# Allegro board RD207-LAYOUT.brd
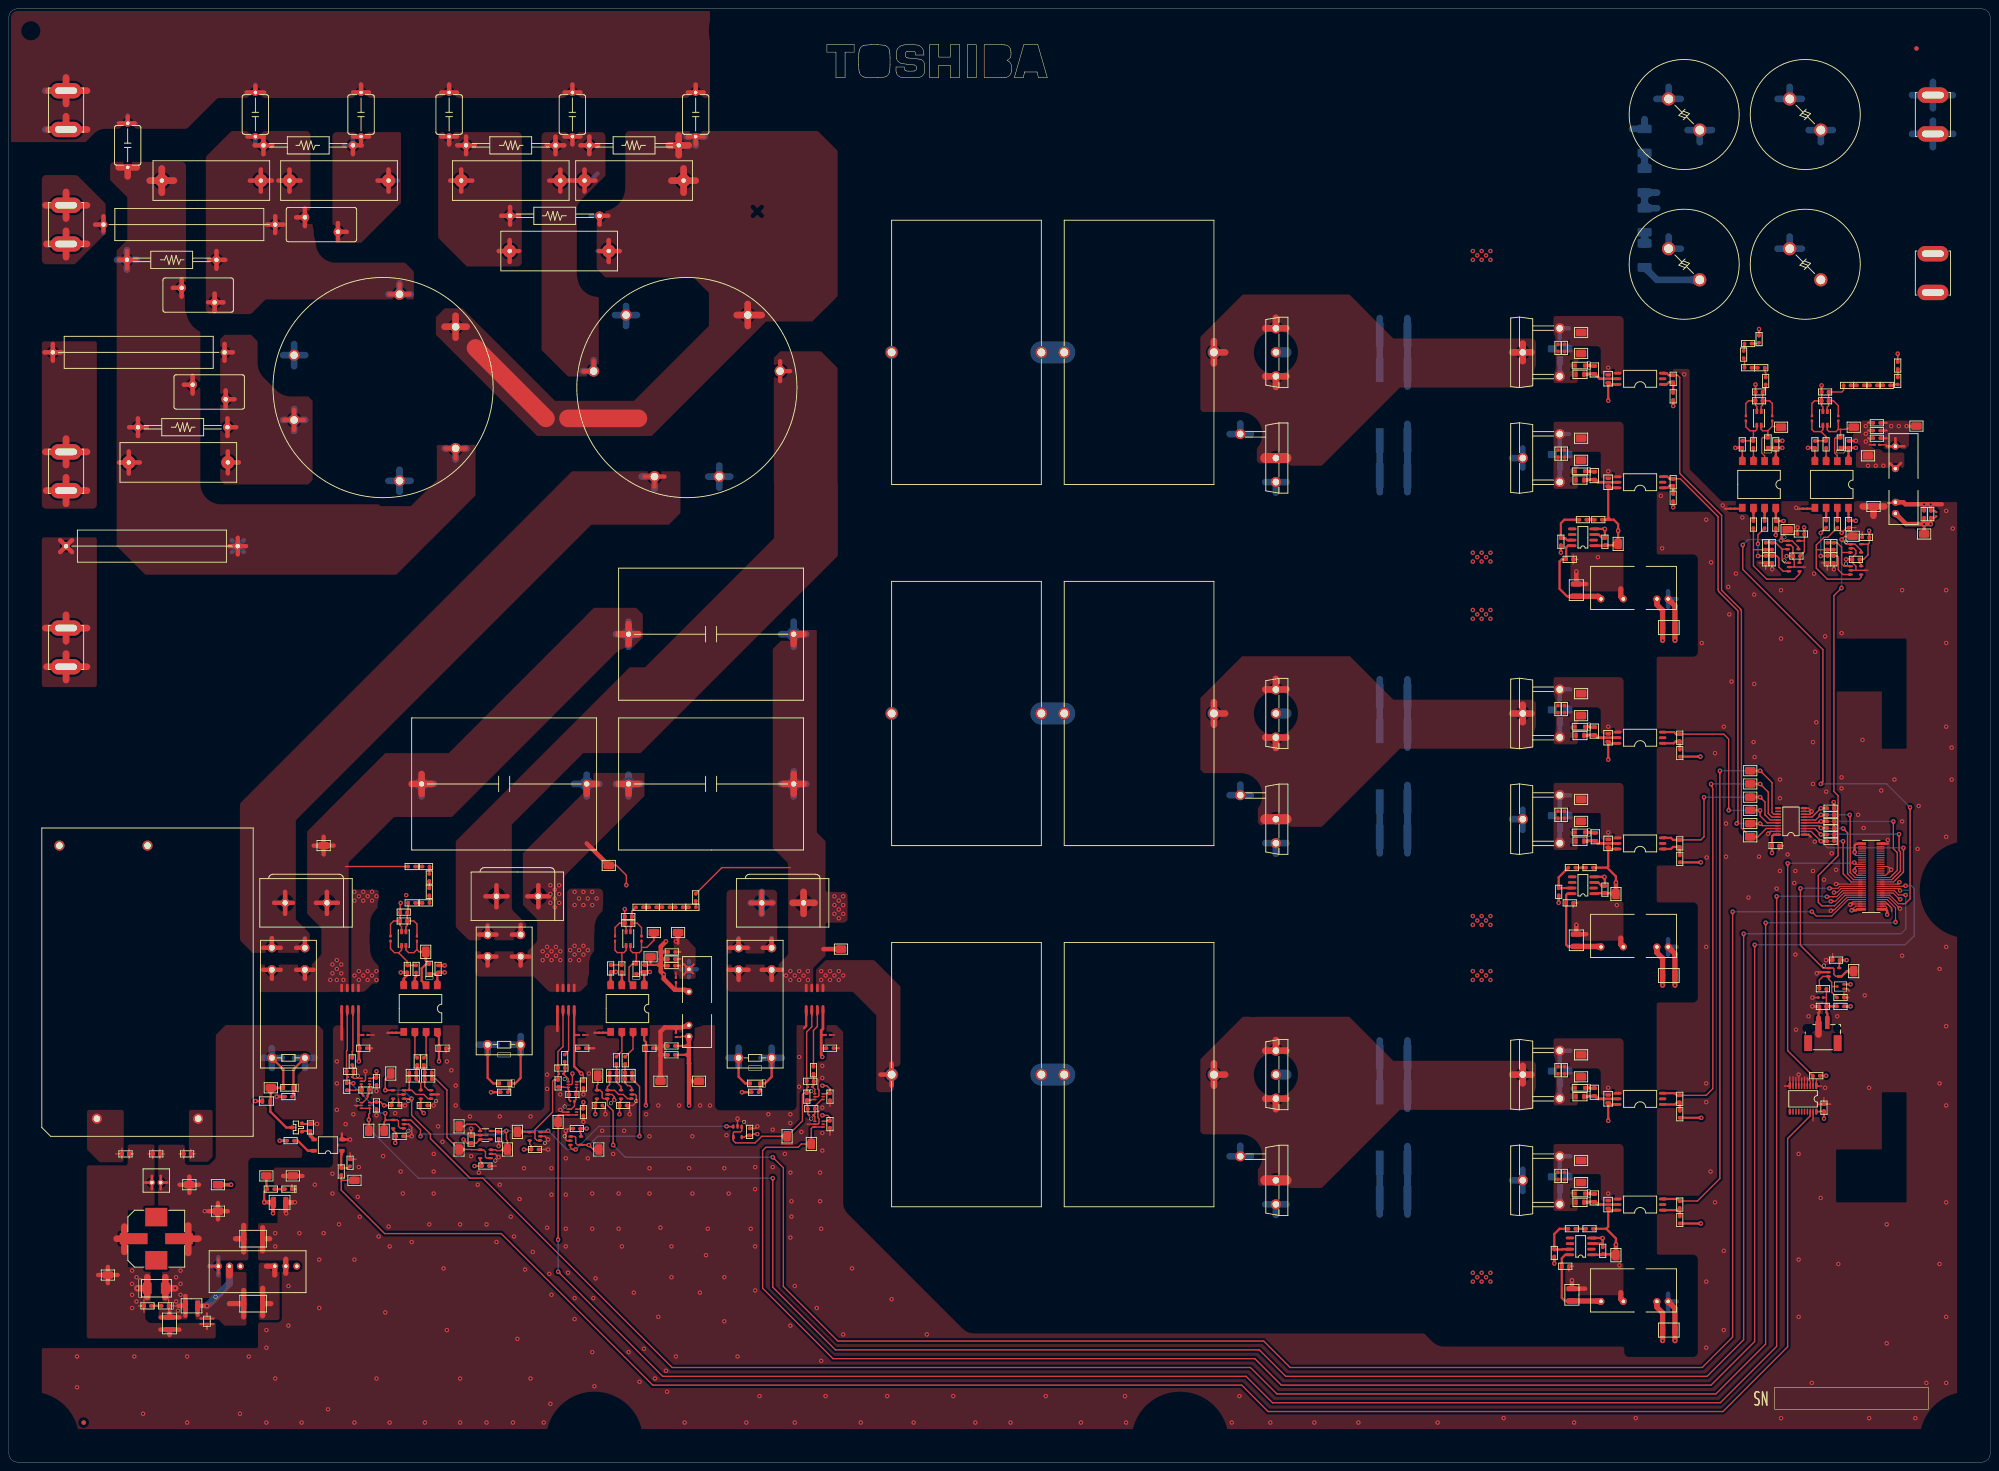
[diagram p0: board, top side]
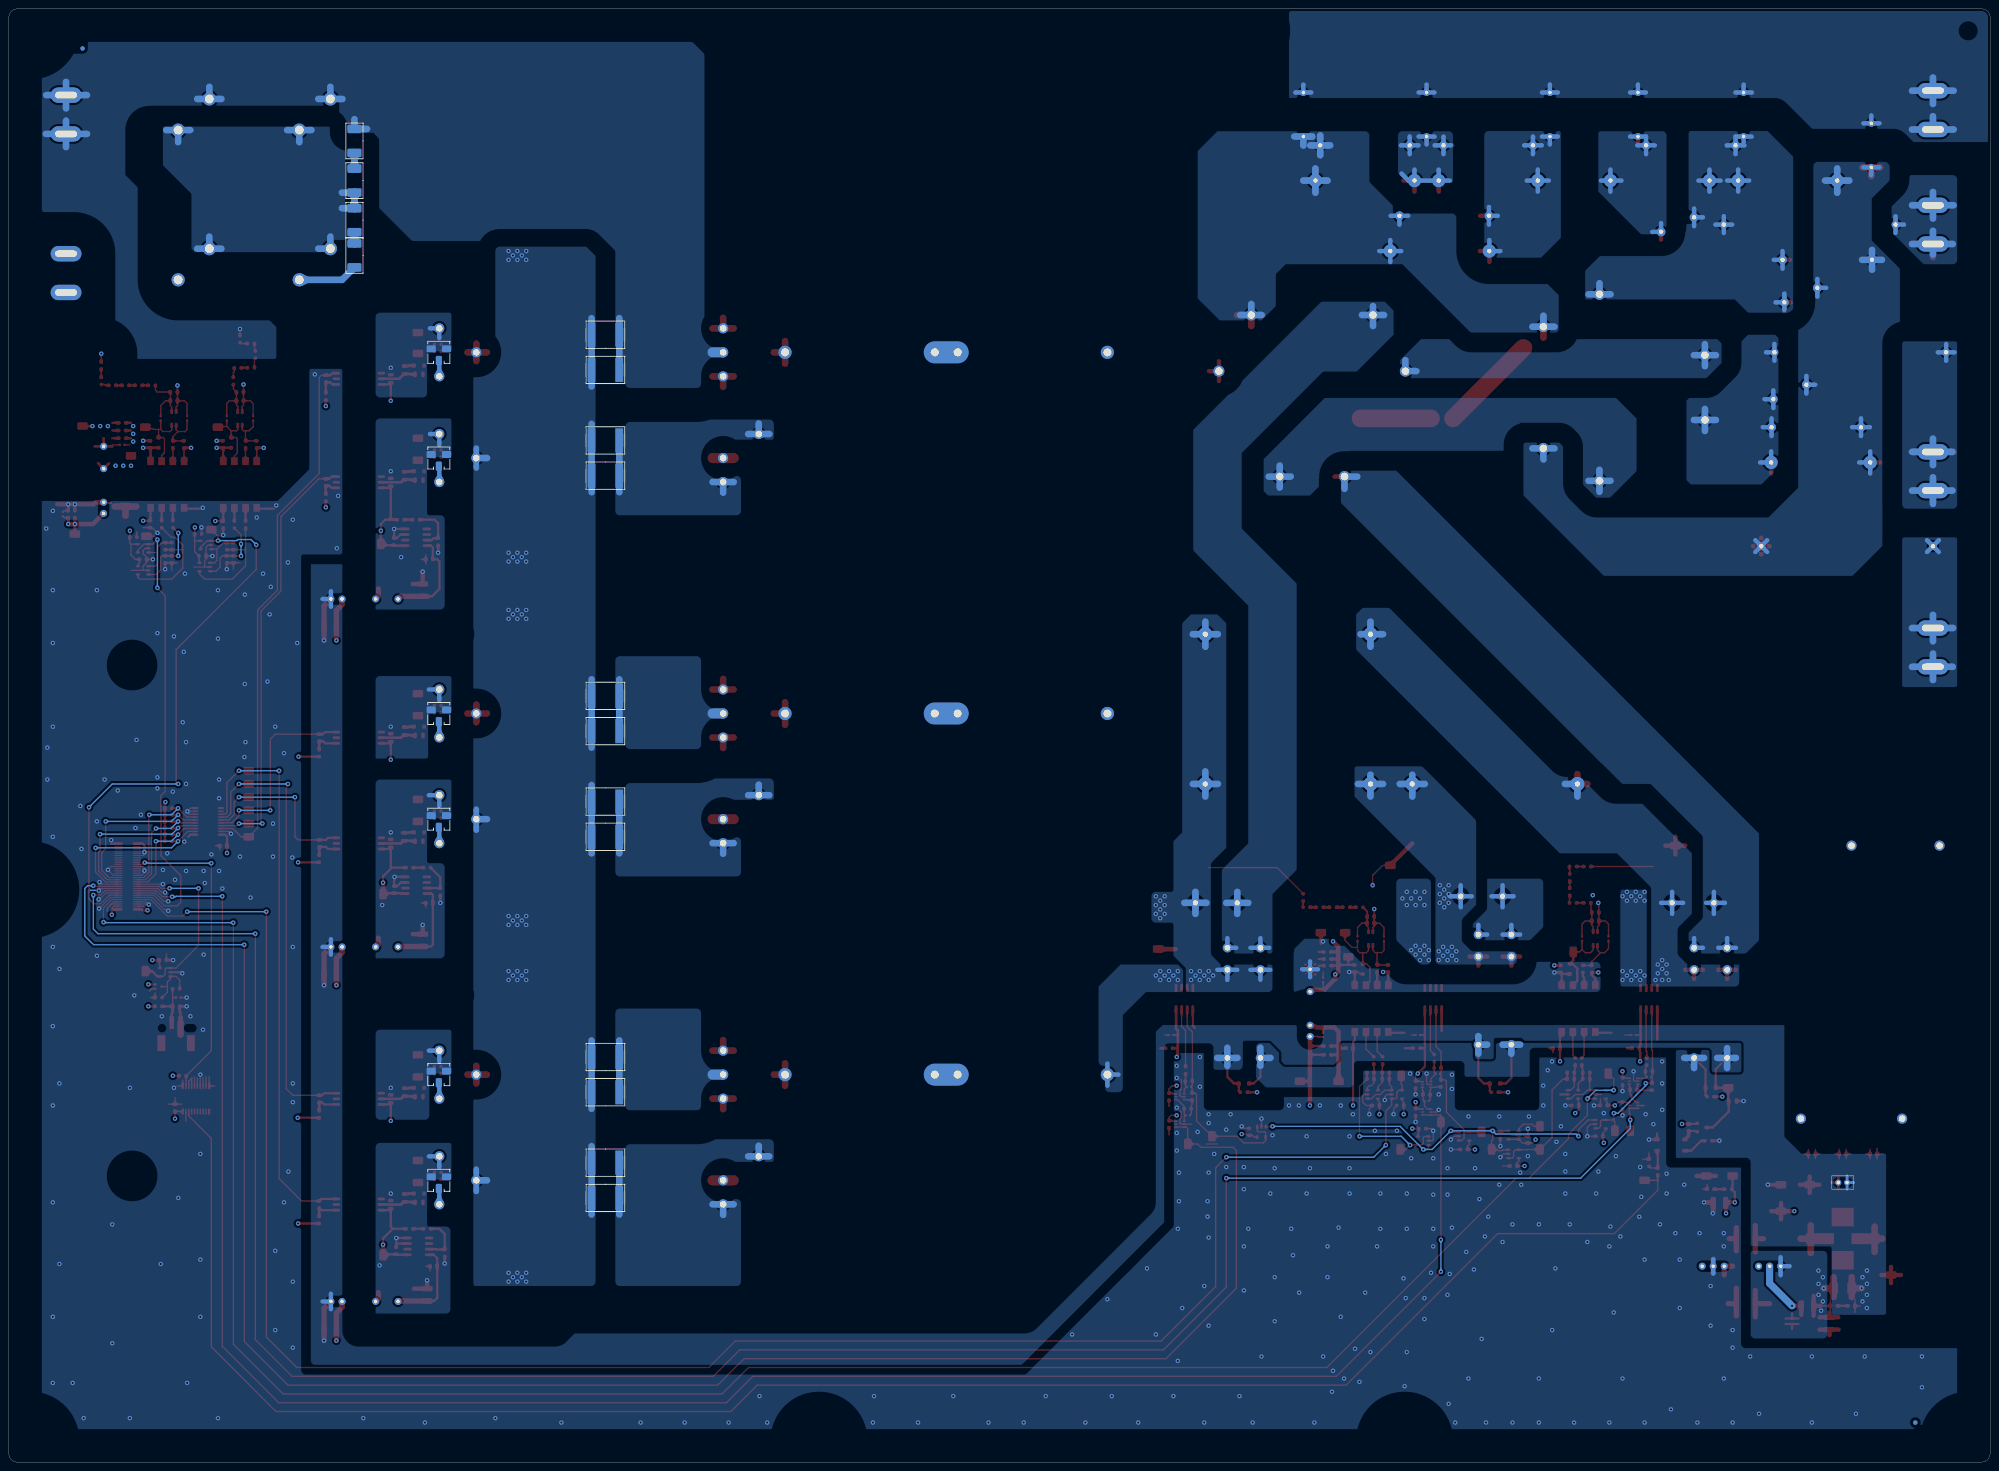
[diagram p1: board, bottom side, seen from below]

Outline 450 x 330 mm; copper layers: TOP, CONDUCTIVE2, CONDUCTIVE3, BOTTOM. Coordinates in mm from the lower left corner of the outline.
Outline path: 0,328 0.03,328.35 0.12,328.68 0.27,329 0.47,329.29 0.71,329.53 1,329.73 1.32,329.88 1.65,329.97 2,330 448,330 448.35,329.97 448.68,329.88 449,329.73 449.29,329.53 449.53,329.29 449.73,329 449.88,328.68 449.97,328.35 450,328 450,2 449.97,1.65 449.88,1.32 449.73,1 449.53,0.71 449.29,0.47 449,0.27 448.68,0.12 448.35,0.03 448,0 1.96,0 1.19,0.16 0.57,0.57 0.14,1.23 0,1.96 0,328

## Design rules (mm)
constraint set DEFAULT: 

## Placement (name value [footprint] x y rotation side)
C1  -  [C_S_1608]  63.5 83 180 top
C2  -  [_C_D_E22_5D0_8W9H18L_1]  75 291 0 top
C3  -  [_C_D_E22_5D0_8W9H18L_1]  46 291 180 top
C4  -  [_C_D_E22_5D0_8W9H18L_1]  114 291 180 top
C5  -  [_C_D_E22_5D0_8W9H18L_1]  142 291 0 top
C6  -  [C_D_F340X1_L42_W30_H_1]  112.5 154 0 top
C7  -  [C_D_F340X1_L42_W30_H_1]  159.5 188 0 top
C8  -  [C_S_1608]  112.5 84 180 top
C9  -  [C_D_F340X1_L42_W30_H_1]  159.5 154 0 top
C10  -  [_C_D_E22_5D0_8W9H18L_1]  38.5 227 180 top
C11  -  [_C_D_E22_5D0_8W9H18L_1]  125 275 0 top
C12  -  [C_S_1608]  169.5 84 180 top
C13  -  [C_D_10_0_CD45_D9_0_T_1]  56 306 90 top
C14  -  [C_D_10_0_CD45_D9_0_T_1]  80 306 90 top
C15  -  [C_D_10_0_CD45_D9_0_T_1]  27 299 90 top
C16  -  [C_D_10_0_CD45_D9_0_T_1]  128 306 90 top
C17  -  [C_D_10_0_CD45_D9_0_T_1]  100 306 90 top
C18  -  [C_D_10_0_CD45_D9_0_T_1]  156 306 90 top
C19  -  [C_S_1608]  33.5 70 0 top
C20  -  [CA_S_D12_5_L13_160CL_1]  33.5 50.75 0 top
C21  -  [C_S_3225]  36.5 31.5 90 top
C22  -  [C_S_3225]  41.5 35.5 180 top
C23  -  [C_S_3225]  61.5 59 0 top
C24  -  [C_S_1608]  80.5 94 0 top
C25  -  [C_S_1005]  81 97 0 top
C26  -  [C_S_6050_CA572_TDK]  314.5 256 0 bottom
C27  -  [C_S_6050_CA572_TDK]  314.5 248 0 bottom
C28  -  [C_S_6050_CA572_TDK]  314.5 174 0 bottom
C29  -  [C_S_6050_CA572_TDK]  314.5 166 0 bottom
C30  -  [C_S_6050_CA572_TDK]  314.5 84 0 bottom
C31  -  [C_S_6050_CA572_TDK]  314.5 92 0 bottom
C32  -  [CA_D_D25_0_L55_0_MXK]  380.5 306 270 top
C33  -  [CA_D_D25_0_L55_0_MXK]  408 306 270 top
C34  -  [C_S_6050_CA572_TDK]  314.5 224 180 bottom
C35  -  [C_S_1005]  130 97 0 top
C36  -  [C_S_6050_CA572_TDK]  314.5 232 180 bottom
C37  -  [C_S_1608]  130.25 94 0 top
C38  -  [C_S_1608]  186.5 94 0 top
C39  -  [C_S_1005]  186 97 0 top
C40  -  [C_S_6050_CA572_TDK]  314.5 150 180 bottom
C41  -  [C_S_6050_CA572_TDK]  314.5 142 180 bottom
C42  -  [CA_D_D25_0_L55_0_MXK]  380.5 272 270 top
C43  -  [CA_D_D25_0_L55_0_MXK]  408 272 270 top
C44  -  [C_S_6050_CA572_TDK]  314.5 60 180 bottom
C45  -  [C_S_6050_CA572_TDK]  314.5 68 180 bottom
C46  -  [C_S_1005]  81 83.25 0 top
C47  -  [C_S_1005]  77.5 87.5 0 top
C48  -  [C_S_1608]  415 114 180 top
C50  -  [C_S_1608]  111.25 74.25 270 top
C51  -  [C_S_1608]  105 73.25 90 top
C52  -  [C_S_1005]  411.5 105.5 180 top
C53  -  [C_S_1608]  416 105.5 0 top
C54  -  [C_S_1005]  125.45 88.2 0 top
C55  -  [C_S_1005]  182 85.25 180 top
C56  -  [C_S_1005]  182.25 78.75 180 top
C57  -  [C_S_1005]  128 82 0 top
C58  -  [C_S_2012]  363.25 246 90 top
C59  -  [C_S_1608]  351.83 253 90 top
C60  -  [C_S_2012]  363.25 222.5 90 top
C61  -  [C_S_1608]  351.83 229 90 top
C62  -  [C_S_3225]  377 189.5 180 top
C63  -  [C_S_3225]  356 198 90 top
C64  -  [C_S_1608]  354.5 205 0 top
C65  -  [C_S_1608]  362.5 209 90 top
C66  -  [C_S_2012]  363.25 164.5 90 top
C67  -  [C_S_1608]  351.83 171 90 top
C68  -  [C_S_2012]  363.25 140.5 90 top
C69  -  [C_S_1608]  351.83 147 90 top
C70  -  [C_S_3225]  377 110.5 180 top
C71  -  [C_S_3225]  356 118.5 90 top
C72  -  [C_S_1608]  354.5 127 0 top
C73  -  [C_S_1608]  362.5 130 90 top
C74  -  [C_S_2012]  363.25 82.5 90 top
C75  -  [C_S_1608]  351.83 89 90 top
C76  -  [C_S_2012]  363.25 58.5 90 top
C77  -  [C_S_1608]  351.83 65 90 top
C78  -  [C_S_3225]  377 30 180 top
C79  -  [C_S_3225]  355 38 90 top
C80  -  [C_S_1608]  353.5 44.5 0 top
C81  -  [C_S_1608]  362 48 90 top
C84  -  [C_S_1608]  97.5 112 90 top
C85  -  [C_S_1608]  98.5 94 0 top
C86  -  [C_S_1608]  89.69 122.89 180 top
C88  -  [C_S_1608]  144.31 112.11 90 top
C89  -  [C_S_1608]  145.5 94 0 top
C91  -  [C_S_1608]  140.69 122.39 180 top
C93  -  [C_S_1608]  108.25 67.25 0 top
C94  -  [C_S_1608]  150.5 114.25 180 top
C95  -  [C_S_1608]  150.5 112.75 180 top
C96  -  [C_S_1005]  151.5 109.5 270 top
C97  -  [C_S_1005]  151.5 97 90 top
C98  -  [C_S_1608]  150.5 94.5 180 top
C99  -  [C_S_1608]  150.5 92.5 180 top
C101  -  [C_S_1608]  401.31 212.89 270 top
C102  -  [C_S_1608]  400.5 208 270 top
C103  -  [C_S_1608]  401.31 231.11 90 top
C104  -  [C_S_1608]  397.5 241 180 top
C105  -  [C_S_1608]  400.5 205 270 top
C106  -  [C_S_1608]  417.81 231.11 90 top
C107  -  [C_S_1608]  417.83 213 270 top
C108  -  [C_S_1608]  413 205 90 top
C109  -  [C_S_1608]  412.5 241 180 top
C110  -  [C_S_1608]  413 208 90 top
C111  -  [C_S_1608]  424.25 234.25 180 top
C112  -  [C_S_1608]  424.25 232.5 180 top
C113  -  [C_S_1005]  424.25 231 180 top
C114  -  [C_S_1005]  437.75 215.25 90 top
C115  -  [C_S_1608]  436.5 215.25 90 top
C116  -  [C_S_1608]  435 215.25 90 top
C117  -  [C_S_1608]  401.25 140 0 top
C118  -  [C_S_1608]  412.25 80.5 90 top
C119  -  [C_S_4532_T2_5]  55.5 36 0 top
C120  -  [C_S_4532_T2_5]  55.5 50.75 0 top
C121  -  [C_S_1608]  87.75 81 0 top
C122  -  [C_S_1608]  94.25 81 0 top
C123  -  [C_S_1608]  134 81 0 top
C124  -  [C_S_1608]  139.5 81 0 top
C125  -  [C_S_1608]  129 75.75 180 top
C126  -  [C_S_1608]  407 210.75 180 top
C127  -  [C_S_1608]  406 205.75 180 top
C128  -  [C_S_1608]  421.75 210 180 top
C129  -  [C_S_1608]  419.5 205 180 top
C140  -  [C_S_1608]  88.75 74 0 top
C141  -  [C_S_1608]  119.5 71 0 top
C142  -  [C_S_1608]  168.25 75 90 top
C143  -  [C_S_1608]  83.5 81 270 top
C144  -  [C_S_1608]  83.5 86.5 270 top
C146  -  [C_S_1608]  130.5 79.5 270 top
C147  -  [C_S_1608]  130.5 85.75 270 top
C149  -  [C_S_1608]  186.5 76.75 270 top
C150  -  [C_S_1608]  186.5 83 270 top
C151  -  [C_S_1608]  95.25 87 0 top
C152  -  [C_S_1608]  91.75 87 0 top
C153  -  [C_S_1608]  140.75 87 0 top
C154  -  [C_S_1608]  137.25 87 0 top
CN1  -  [CN_D_B02B_PASK]  33.5 63.5 180 top
CN2  -  [CN_S_6_1460820_X_SP__1]  352.33 252 270 bottom
CN3  -  [CN_S_6_1460820_X_SP__1]  352.33 228 270 bottom
CN4  -  [CN_S_6_1460820_X_SP__1]  352.33 170 270 bottom
CN5  -  [CN_S_6_1460820_X_SP__1]  352.33 146 270 bottom
CN6  -  [CN_S_6_1460820_X_SP__1]  352.33 88 270 bottom
CN7  -  [CN_S_6_1460820_X_SP__1]  352.33 64 270 bottom
CN8  -  [CN_S_BM02B_PASS_1_TF_1]  412 96.5 0 top
CN9  -  [CN_S_WR_60S_VFH05_N1]  423 133 90 top
CT1  -  [IC_SOP8_1_27_D]  77.5 105.25 180 top
CT2  -  [IC_SOP8_1_27_D]  126.5 105.25 180 top
CT3  -  [IC_SOP8_1_27_D]  183 105.25 180 top
D1  -  [D_S_1_1E1A_USC_AC]  63.5 85 0 top
D2  -  [D_S_1_1E1A_USC_AC]  112.5 86 0 top
D3  -  [D_S_1_1E1A_USC_AC]  169.5 86 0 top
D4  -  [D_D_TO_247_3_1A2C3A]  287.77 252 270 top
D5  -  [D_D_TO_247_3_1A2C3A]  287.77 170 270 top
D6  -  [D_D_TO_247_3_1A2C3A]  287.77 88 270 top
D7  -  [D_D_TO_247_3_1A2C3A__1]  287.77 228 270 top
D8  -  [D_D_TO_247_3_1A2C3A__1]  287.77 64 270 top
D9  -  [D_D_TO_247_3_1A2C3A__1]  287.77 146 270 top
D10  -  [_D_S_EMD3_SOT_416_SC_1]  416 108 180 top
D11  -  [D_S_1_1E1A_USC_AC]  356.83 249 0 top
D12  -  [D_S_1_1E1A_USC_AC]  356.83 225 0 top
D13  -  [D_S_1_1E1A_USC_AC]  356.83 167 0 top
D14  -  [D_S_1_1E1A_USC_AC]  356.83 143 0 top
D15  -  [D_S_1_1E1A_USC_AC]  356.83 85 0 top
D16  -  [D_S_1_1E1A_USC_AC]  356.83 61 0 top
D17  -  [D_S_1_1E1A_USC_AC]  95.5 112 270 top
D18  -  [D_S_1_1E1A_USC_AC]  142.5 112 270 top
D19  -  [D_S_1_1E1A_USC_AC]  399.5 231.5 270 top
D20  -  [D_S_1_1E1A_USC_AC]  416 231.5 270 top
F1  -  [F_D_0505XXXX_10A_16A]  41 281 0 top
F2  -  [F_D_0505XXXX_10A_16A]  29.5 252 0 top
F3  -  [F_D_0505XXXX_10A_16A]  32.5 208 0 top
IC1  -  [_IC_SOP5_P_0_95_DDC]  108.25 74.25 180 top
IC2  -  [IC_SOP5_0_95_SOT_25]  414.5 111.25 270 top
IC4  -  [IC_SOP8_1_27_D]  357.5 210 90 top
IC5  -  [IC_SOP8_1_27_D]  357.5 131 90 top
IC6  -  [IC_SOP8_1_27_D]  357 49 90 top
IC8  -  [IC_SOP8_2_54_11_10C4_1]  93.5 103 180 top
IC9  -  [IC_SOP8_2_54_11_10C4_1]  140.5 103 180 top
IC10  -  [IC_SOP5_0_95_SOT_25]  108.25 70 90 top
IC12  -  [IC_SOP8_2_54_11_10C4_1]  397.5 222 180 top
IC13  -  [IC_SOP8_2_54_11_10C4_1]  414 222 180 top
IC14  -  [IC_SOP20_0_65_FT]  404.75 145.5 90 top
IC15  -  [IC_SOP20_0_65_FT]  407.5 82.5 180 top
IC16  -  [IC_SOP5_0_95_SOT_25]  88.5 83.5 90 top
IC17  -  [IC_SOP5_0_95_SOT_25]  94.75 83.5 90 top
IC18  -  [IC_SOP5_0_95_SOT_25]  134.75 83.5 90 top
IC19  -  [IC_SOP5_0_95_SOT_25]  140.25 83.5 90 top
IC20  -  [IC_SOP5_0_95_SOT_25]  128.75 73 270 top
IC21  -  [IC_SOP5_0_95_SOT_25]  405.25 208.25 270 top
IC22  -  [IC_SOP5_0_95_SOT_25]  405.5 203.25 270 top
IC23  -  [IC_SOP5_0_95_SOT_25]  419.5 207.5 270 top
IC24  -  [IC_SOP5_0_95_SOT_25]  419.5 202.5 270 top
IC28  -  [IC_SOP5_0_95_SOT_25]  88.5 76.75 90 top
IC29  -  [IC_SOP5_0_95_SOT_25]  119.5 74 90 top
IC30  -  [IC_SOP5_0_95_SOT_25]  165.5 75 180 top
IC31  -  [IC_SOP6_0_65_DCK]  81 81 270 top
IC32  -  [IC_SOP6_0_65_DCK]  81 86.5 270 top
IC33  -  [IC_SOP6_0_65_DCK]  128 79.5 270 top
IC34  -  [IC_SOP6_0_65_DCK]  128 85.75 270 top
IC35  -  [IC_SOP6_0_65_DCK]  184 76.75 270 top
IC36  -  [IC_SOP6_0_65_DCK]  184 83 270 top
L1  -  [L_D_CFA37H_40210R0]  85 244 330 top
L2  -  [L_D_CFA37H_40210R0]  154 244 60 top
L3  -  [L_S_MBKK1608]  45 32 90 top
L4  -  [L_D_HKBS_24D160]  217.5 252 270 top
L5  -  [L_D_HKBS_24D160]  256.7 252 270 top
L6  -  [L_D_HKBS_24D160]  217.5 170 270 top
L7  -  [L_D_HKBS_24D160]  256.7 170 270 top
L8  -  [L_D_HKBS_24D160]  217.5 88 270 top
L9  -  [L_D_HKBS_24D160]  256.7 88 270 top
L10  -  [L_S_ACT1210]  89.69 118.89 270 top
L11  -  [L_S_ACT1210]  140.69 118.89 270 top
L12  -  [L_S_ACT1210]  397.5 237 270 top
L13  -  [L_S_ACT1210]  412.5 237 270 top
L14  -  [L_S_1005]  87.5 97.5 180 top
L15  -  [L_S_1005]  134.5 97.5 180 top
L16  -  [L_S_1005]  391.5 216.5 180 top
L17  -  [L_S_1005]  408 216.5 180 top
LED1  -  [LED_S_1608_AC]  35.5 35.5 0 top
LED2  -  [LED_S_1608_AC]  63.5 62 0 top
NOREF  -  [unnamed]  270 325 0 top
NOREF#2  -  [unnamed]  348.8 188 0 top
NOREF#3  -  [unnamed]  154.5 103 0 top
NOREF#4  -  [unnamed]  370.5 119.5 90 top
NOREF#5  -  [unnamed#2]  423 133 270 top
NOREF#6  -  [unnamed]  445 130 0 top
NOREF#7  -  [unnamed]  445 230 0 top
NOREF#8  -  [unnamed]  183 105.25 0 top
NOREF#9  -  [unnamed]  428.5 222 0 top
NOREF#10  -  [unnamed]  445 325 0 top
NOREF#11  -  [#3]  396 12 0 top
NOREF#12  -  [unnamed]  237.1 211 0 top
NOREF#13  -  [unnamed]  370.5 198.5 90 top
NOREF#14  -  [unnamed]  5 165 0 top
NOREF#15  -  [unnamed]  5 325 0 top
NOREF#16  -  [unnamed]  5 5 0 top
NOREF#17  -  [unnamed]  170 325 0 top
NOREF#18  -  [unnamed]  5 60 0 top
NOREF#19  -  [unnamed]  445 5 0 top
NOREF#20  -  [unnamed]  237.1 47 0 top
NOREF#21  -  [unnamed]  282.8 188 0 top
NOREF#22  -  [unnamed]  348.8 270 0 top
NOREF#23  -  [#3]  185.8 314.35 0 top
NOREF#24  -  [unnamed]  126.5 105.25 0 top
NOREF#25  -  [unnamed]  282.8 106 0 top
NOREF#26  -  [unnamed]  370.5 39 90 top
NOREF#27  -  [unnamed]  133 5 0 top
NOREF#28  -  [unnamed]  237.1 293 0 top
NOREF#29  -  [unnamed]  237.1 129 0 top
NOREF#30  -  [unnamed]  77.5 105.25 0 top
NOREF#31  -  [#3]  17 9 90 top
NOREF#32  -  [unnamed]  282.8 270 0 top
NOREF#33  -  [unnamed]  348.8 106 0 top
NOREF#34  -  [#3]  433.25 321 90 top
NOREF#35  -  [unnamed]  266 5 0 top
PC1  -  [IC_SOP6_1_27_11_4N10_1]  370.5 246 90 top
PC2  -  [IC_SOP6_1_27_11_4N10_1]  370.5 222.5 90 top
PC3  -  [IC_SOP6_1_27_11_4N10_1]  370.5 164.5 90 top
PC4  -  [IC_SOP6_1_27_11_4N10_1]  370.5 140.5 90 top
PC5  -  [IC_SOP6_1_27_11_4N10_1]  370.5 82.5 90 top
PC6  -  [IC_SOP6_1_27_11_4N10_1]  370.5 58.5 90 top
PC7  -  [IC_SOP4_2_54_11_4M1S]  72.5 72 90 top
PS1  -  [IC_D_LD20_26BXX]  31.5 109 270 top
PS2  -  [PS_D_EC5SAW]  56.5 43.25 0 top
PS3  -  [IC_D_RXXP2XXS]  369 196 180 top
PS4  -  [IC_D_RXXP2XXS]  369 117 180 top
PS5  -  [IC_D_RXXP2XXS]  369 36.5 180 top
PS6  -  [IC_D_MEF1_SP3C]  156 105.5 90 top
PS7  -  [IC_D_MEF1_SP3C]  430 224.25 90 top
Q1  -  [Q_D_TO_247_3_GDS_TO__1]  343.83 252 90 top
Q2  -  [Q_D_TO_247_3_GDS_TO__1]  343.83 228 90 top
Q3  -  [Q_D_TO_247_3_GDS_TO__1]  343.83 170 90 top
Q4  -  [Q_D_TO_247_3_GDS_TO__1]  343.83 146 90 top
Q5  -  [Q_D_TO_247_3_GDS_TO__1]  343.83 88 90 top
Q6  -  [Q_D_TO_247_3_GDS_TO__1]  343.83 64 90 top
Q7  -  [Q_S_SOT_23F_GSD]  65.5 76 90 top
R1  -  [R_D_MNG12E]  67.5 127 180 top
R2  -  [R_D_RCR60_9_5X3_5]  68 299 180 top
R3  -  [R_D_RCR60_9_5X3_5]  37 273 0 top
R4  -  [R_D_RCR60_9_5X3_5]  114 299 0 top
R5  -  [R_D_RCR60_9_5X3_5]  142 299 180 top
R6  -  [R_D_MNG12E]  115.5 128.5 180 top
R7  -  [R_D_RCR60_9_5X3_5]  124 283 180 top
R8  -  [R_D_RCR60_9_5X3_5]  39.5 235 0 top
R9  -  [R_D_MNG12E]  175.75 127 180 top
R10  -  [R_S_1608]  26.5 70 0 top
R11  -  [R_S_1608]  31.5 35.5 0 top
R12  -  [R_S_1608]  40.5 70 180 top
R13  -  [R_S_1608]  59.5 62 0 top
R14  -  [R_S_6432_T1_25]  371.5 300 90 bottom
R15  -  [R_S_6432_T1_25]  371.5 291 90 bottom
R16  -  [R_S_6432_T1_25]  371.5 282 90 bottom
R17  -  [R_S_6432_T1_25]  371.5 274 90 bottom
R18  -  [R_S_1608]  76.75 85.25 270 top
R19  -  [R_S_1608]  81 84.5 180 top
R20  -  [R_S_1608]  416 103.5 0 top
R21  -  [R_S_1608]  77.5 88.75 180 top
R22  -  [R_S_1608]  412 107.5 0 top
R23  -  [R_S_1608]  78 91 270 top
R24  -  [R_S_1608]  412 103.5 0 top
R25  -  [R_S_1608]  126.25 91.75 270 top
R26  -  [R_S_1608]  182.75 89 90 top
R27  -  [R_S_1608]  182 86.5 0 top
R28  -  [R_S_1608]  125.5 89.5 180 top
R29  -  [R_S_1608]  182.25 80.25 0 top
R30  -  [R_S_1608]  124.75 86 270 top
R31  -  [R_S_1608]  128 83.5 180 top
R32  -  [R_S_1608]  181.25 83 270 top
R33  -  [R_S_1608]  378 242 90 top
R34  -  [R_S_2012]  360.08 248 90 top
R35  -  [R_S_1608]  378 246 90 top
R36  -  [R_S_2012]  356.83 247 180 top
R37  -  [R_S_1608]  353.33 253 270 top
R38  -  [R_S_1608]  378 219 90 top
R39  -  [R_S_2012]  360.08 224 90 top
R40  -  [R_S_1608]  378 222.5 90 top
R41  -  [R_S_2012]  356.83 223 180 top
R42  -  [R_S_1608]  353.33 229 270 top
R43  -  [R_S_1608]  361 214 0 top
R44  -  [R_S_1608]  357.5 214 180 top
R45  -  [R_S_1608]  352.5 209 90 top
R46  -  [R_S_1608]  379.5 161 90 top
R47  -  [R_S_2012]  360.08 166 90 top
R48  -  [R_S_1608]  379.5 164.5 90 top
R49  -  [R_S_2012]  356.83 165 180 top
R50  -  [R_S_1608]  353.33 171 270 top
R51  -  [R_S_1608]  379.5 137 90 top
R52  -  [R_S_2012]  360.33 142 90 top
R53  -  [R_S_1608]  379.5 140.5 90 top
R54  -  [R_S_2012]  356.83 141 180 top
R55  -  [R_S_1608]  353.33 147 270 top
R56  -  [R_S_1608]  359 135 0 top
R57  -  [R_S_1608]  355 135 180 top
R58  -  [R_S_1608]  352 129.5 90 top
R59  -  [R_S_1608]  379.5 79 90 top
R60  -  [R_S_2012]  360.08 84 90 top
R61  -  [R_S_1608]  379.5 82.5 90 top
R62  -  [R_S_2012]  356.83 83 180 top
R63  -  [R_S_1608]  353.33 89 270 top
R64  -  [R_S_1608]  379.5 55 90 top
R65  -  [R_S_2012]  360.08 60 90 top
R66  -  [R_S_1608]  379.5 58.5 90 top
R67  -  [R_S_2012]  356.83 59 180 top
R68  -  [R_S_1608]  353.33 65 270 top
R69  -  [R_S_1608]  359 53 0 top
R70  -  [R_S_1608]  355 53 180 top
R71  -  [R_S_1608]  351 47.5 90 top
R72  -  [R_S_1608]  94.75 135.25 0 top
R73  -  [R_S_1608]  95.5 129.5 270 top
R75  -  [R_S_1608]  91.5 135.25 0 top
R76  -  [R_S_1608]  95.5 132.75 270 top
R77  -  [R_S_1608]  91.5 127 180 top
R78  -  [R_S_1608]  94.75 127 180 top
R79  -  [R_S_1005]  92.69 118.89 270 top
R80  -  [R_S_1608]  89.69 124.89 0 top
R81  -  [R_S_1608]  94.25 91 270 top
R82  -  [R_S_1608]  92.5 112 270 top
R83  -  [R_S_1608]  92.75 91 270 top
R84  -  [R_S_1608]  90.5 112 270 top
R86  -  [R_S_1005]  86.69 118.89 270 top
R87  -  [R_S_1608]  156 128.25 270 top
R88  -  [R_S_1608]  155.25 126 180 top
R89  -  [R_S_1608]  152.25 126 180 top
R90  -  [R_S_1608]  149.25 126 180 top
R91  -  [R_S_1608]  146.25 126 180 top
R92  -  [R_S_1608]  143.25 126 180 top
R93  -  [R_S_1005]  143.69 118.89 270 top
R95  -  [R_S_1608]  140.69 123.89 0 top
R96  -  [R_S_1608]  140 91.25 270 top
R97  -  [R_S_1608]  139.23 112.11 270 top
R98  -  [R_S_1608]  138 91.25 270 top
R99  -  [R_S_1608]  136.69 112.11 270 top
R101  -  [R_S_1005]  137.69 118.89 270 top
R102  -  [R_S_1608]  395 254 180 top
R103  -  [R_S_1005]  400.5 237 270 top
R104  -  [R_S_1608]  399 208 90 top
R105  -  [R_S_1608]  397.5 255 270 top
R106  -  [R_S_1608]  395 248.5 0 top
R107  -  [R_S_1608]  399 245.5 270 top
R108  -  [R_S_1608]  394 251.5 270 top
R109  -  [R_S_1608]  398 248.5 0 top
R110  -  [R_S_1608]  397.5 243 0 top
R111  -  [R_S_1608]  398.77 212.89 270 top
R112  -  [R_S_1608]  396.23 231.11 90 top
R113  -  [R_S_1608]  396.23 212.89 270 top
R114  -  [R_S_1608]  393.69 231.11 270 top
R115  -  [R_S_1608]  399 205 90 top
R116  -  [R_S_1005]  394.5 237 270 top
R117  -  [R_S_1608]  429 249 270 top
R118  -  [R_S_1608]  429 245.5 270 top
R119  -  [R_S_1608]  426.5 244.5 180 top
R120  -  [R_S_1608]  423.5 244.5 180 top
R121  -  [R_S_1608]  420.5 244.5 180 top
R122  -  [R_S_1608]  417.5 244.5 180 top
R123  -  [R_S_1005]  415.5 237 270 top
R124  -  [R_S_1608]  414.5 205 270 top
R125  -  [R_S_1608]  412.5 243 0 top
R126  -  [R_S_1608]  415.29 213 270 top
R127  -  [R_S_1608]  412.73 231.11 90 top
R128  -  [R_S_1608]  412.75 213 270 top
R129  -  [R_S_1608]  410.19 231.11 270 top
R130  -  [R_S_1608]  414.5 208 270 top
R131  -  [R_S_1005]  409.5 237 270 top
R132  -  [R_S_1608]  413.75 141 0 top
R133  -  [R_S_1608]  413.75 142.5 0 top
R134  -  [R_S_1608]  413.75 144 0 top
R135  -  [R_S_1608]  413.75 145.5 0 top
R136  -  [R_S_1608]  413.75 147 0 top
R137  -  [R_S_1608]  413.75 148.5 0 top
R138  -  [R_S_1608]  410.5 87.75 0 top
R139  -  [R_S_2012]  58.5 82 180 top
R140  -  [R_S_1608]  64 73 180 top
R141  -  [R_S_1608]  75.5 66 90 top
R142  -  [R_S_1608]  77.5 68 270 top
R143  -  [R_S_1608]  68.5 76 270 top
R144  -  [R_S_1608]  150.56 115.86 0 top
R145  -  [R_S_1608]  424.25 236 0 top
R146  -  [R_S_1608]  95.25 88.5 180 top
R147  -  [R_S_1608]  91.75 88.5 180 top
R148  -  [R_S_1608]  140.75 88.5 180 top
R149  -  [R_S_1608]  137.25 88.5 180 top
RLY1  -  [RL_D_G2RL_6PIN]  63.5 104 90 top
RLY2  -  [RL_D_G2RL_6PIN]  112.5 107 90 top
RLY3  -  [RL_D_G2RL_6PIN]  169.5 104 90 top
TB1  -  [TB_D_OT_264]  13 281 90 top
TB2  -  [TB_D_OT_264]  13 225 90 top
TB3  -  [TB_D_OT_264]  13 185 90 top
TB4  -  [TB_D_OT_264]  13 307 90 top
TB5  -  [TB_D_OT_264]  437 306 90 top
TB6  -  [TB_D_OT_264]  437 270 90 top
TP1  -  [TP_HK_3_G]  71.5 140 0 top
TP2  -  [TP_HK_3_G]  136.25 135.5 0 top
TP3  -  [TP_HK_3_G]  189 116.5 0 top
TP4  -  [TP_HK_3_G]  22.5 42.5 0 top
TP5  -  [TP_HK_3_G]  41 63 0 top
TP6  -  [TP_HK_3_G]  47.5 63 0 top
TP7  -  [TP_HK_3_G]  58.5 65 0 top
TP8  -  [TP_HK_3_G]  47.5 57 0 top
TP9  -  [TP_HK_3_G]  64.5 65 0 top
TP10  -  [TP_HK_3_G]  419 111.5 270 top
TP11  -  [TP_HK_3_G]  113.25 71 90 top
TP12  -  [TP_HK_3_G]  102.25 76.25 270 top
TP13  -  [TP_HK_3_G]  81.75 75.25 90 top
TP14  -  [TP_HK_3_G]  124.75 77.25 90 top
TP15  -  [TP_HK_3_G]  182.25 72.25 90 top
TP16  -  [TP_HK_3_G]  357.08 251.75 180 top
TP17  -  [TP_HK_3_G]  357.08 256.5 180 top
TP18  -  [TP_HK_3_G]  357.08 227.5 180 top
TP19  -  [TP_HK_3_G]  357.08 232.5 180 top
TP20  -  [TP_HK_3_G]  365.5 208.5 90 top
TP21  -  [TP_HK_3_G]  357.08 169.5 180 top
TP22  -  [TP_HK_3_G]  357.08 174.5 180 top
TP23  -  [TP_HK_3_G]  357.08 145.5 180 top
TP24  -  [TP_HK_3_G]  357.08 150.5 180 top
TP25  -  [TP_HK_3_G]  365 129 90 top
TP26  -  [TP_HK_3_G]  357.08 87.5 180 top
TP27  -  [TP_HK_3_G]  357.08 92.5 180 top
TP28  -  [TP_HK_3_G]  357.08 63.5 180 top
TP29  -  [TP_HK_3_G]  357.08 68.5 180 top
TP30  -  [TP_HK_3_G]  365 47 90 top
TP31  -  [TP_HK_3_G]  86.75 88.25 90 top
TP32  -  [TP_HK_3_G]  94.69 115.89 270 top
TP33  -  [TP_HK_3_G]  146.5 120.25 180 top
TP34  -  [TP_HK_3_G]  133.75 87.75 90 top
TP35  -  [TP_HK_3_G]  152 120.25 0 top
TP36  -  [TP_HK_3_G]  102.25 71 90 top
TP37  -  [TP_HK_3_G]  145.75 114.75 0 top
TP38  -  [TP_HK_3_G]  404 211.75 180 top
TP39  -  [TP_HK_3_G]  402.5 235 180 top
TP40  -  [TP_HK_3_G]  419 235 180 top
TP41  -  [TP_HK_3_G]  418.75 210.25 180 top
TP42  -  [TP_HK_3_G]  433.25 235.25 180 top
TP43  -  [TP_HK_3_G]  422.25 228.5 0 top
TP44  -  [TP_HK_3_G]  395.5 142 180 top
TP45  -  [TP_HK_3_G]  395.5 145 180 top
TP46  -  [TP_HK_3_G]  395.5 148 180 top
TP47  -  [TP_HK_3_G]  395.5 151 180 top
TP48  -  [TP_HK_3_G]  395.5 154 180 top
TP49  -  [TP_HK_3_G]  395.5 157 180 top
TP50  -  [TP_HK_3_G]  59.5 85 0 top
TP51  -  [TP_HK_3_G]  78.5 64 0 top
TP52  -  [TP_HK_3_G]  148 86.5 0 top
TP53  -  [TP_HK_3_G]  156.75 86.5 0 top
TP54  -  [TP_HK_3_G]  423.5 217 0 top
TP55  -  [TP_HK_3_G]  435 210.75 0 top
TP56  -  [TP_HK_3_G]  134 71 90 top
TP62  -  [TP_HK_3_G]  85.25 75.25 90 top
TP63  -  [TP_HK_3_G]  115.5 75 90 top
TP64  -  [TP_HK_3_G]  176.75 74 90 top
ZD1  -  [_D_S_SMB_DO_214AA_AC]  33.5 39.5 180 top
ZNR1  -  [_ZNR_D_TND14V_16_0_7_1]  71 281 180 top
ZNR2  -  [_ZNR_D_TND14V_16_0_7_1]  43 265 0 top
ZNR3  -  [_ZNR_D_TND14V_16_0_7_1]  45.5 243 0 top

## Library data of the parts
C1 C8 C12 C19 C48 C50 C51 C64 C65 C72 C73 C80 C81 C84 C85 C88 C89 C93 C94 C98 C101 C103 C106 C107 C112 C115 C117 C118 C121-C129 C140-C144 C146 C147 C149 C150 = -C-UMK107AB7105KA-T
C2-C5 C10 C11 = -C-F339X142248MIP2T0
C6 C7 C9 = -C-F340X153348MPP2T0
C13-C18 = -C-CD45-E2GA222M-VKA
C20 = -C-MAL216099001E3
C21-C23 C62 C63 C70 C71 C78 C79 = -C-UMK325AB7106KM-T
C24 C37 C38 C95 C99 C111 C116 = -C-GRM188D71A106KA73D
C25 C35 C39 C52 C96 C97 C113 C114 = -C-UMK105BJ104KV-F
C26 C28 C30 C36 C40 C44 = -C-CAA572X7T2J105M640LH
C27 C29 C31 C34 C41 C45 = -C-NC_CAA572X7T2J105M640LH
C32 C33 C42 C43 = -C-450MXK470MEFCSN25X55
C46 C47 C54-C57 = -C-GCM1555C1H270FA16D
C53 C104 C109 = -C-GRM1885C1H102JA01D
C58 C60 C66 C68 C74 C76 = C-UMK212B7105KGHT: alternate symbols: (C58_C_S_2012,C60_C_S_2012,C66_C_S_2012,C68_C_S_2012,C74_C_S_2012,C76_C_S_2012)
C59 C61 C67 C69 C75 C77 = -C-NC_C1608
C86 C91 C102 C105 C108 C110 = -C-GRM1885C1H122JA01J
C119 C120 = -C-C4532CH3F331K250KA
C151-C154 = -C-GCM1885C1H222FA16D
CN1 = -CN-NC_B02B-PASK
CN2-CN7 = CN-6-1460820-1_Micro_SP-NoTH
CN8 = -CN-BM02B-PASS-1-TFT_LF_SN
CN9 = -CN-WR-60S-VFH05-N1
CT1-CT3 = -CT-TMCS1100A2QDR
D1-D3 D17-D20 = -D-BAS316_H3F_AC
D4-D6 = D-TRS15N120HB
D7-D9 = D-TRS15N120HB_SP
D10 = -D-1SS423_TE85L_F_AC
D11-D16 = -D-CUS10F30_AC
F1-F3 = F-0505012.MXEP
IC1 = -IC-REF2025AIDDCT
IC2 IC10 IC16-IC24 IC28-IC30 = IC-TC75S103F
IC4-IC6 = -IC-LP2951D
IC8 IC9 IC12 IC13 = IC-TLP7920F_D4ALF4_F
IC14 = -IC-74VHCT541AFT
IC15 = -IC-74VHCT540AFT
IC31-IC36 = IC-OPA607IDCKR
L1 L2 = L-CFA37H-40210R0
L3 = -L-MBKK1608T1R0M
L4-L9 = L-HKBS-24D160-7510
L10-L13 = -L-ACT1210-101-2P-TL00
L14-L17 = L-NC_LQW15CA22NK00D: alternate symbols: (L14_L_S_1005)
LED1 LED2 = -LED-VCDG1111C-4BY3C-TR_AC
PC1-PC6 = PC-TLP5774H_TP4_E
PC7 = -PC-TLP183_TPL_E
PS1 = PS-LD20-26B24
PS2 = PS-EC5SAW-24S05N
PS3-PS5 = -PS-R24P212S
PS6 PS7 = PS-MEF1S0505SP3C
Q1-Q6 = Q-TK065N65Z_TATE
Q7 = -Q-SSM3K318R
R1 R6 R9 = R-MNG12E740JC
R2-R5 R7 R8 = -R-RCR60C474J
R10 R12 R84 R99 R114 R129 = -R-RK73Z1JTTD
R11 R37 R42 R50 R55 R63 R68 R132-R138 R140 = -R-ERJ3EKF1002V
R13 R22 R35 R40 R48 R53 R61 R66 R142 = -R-RK73H1JTTD1001F
R14-R17 = -R-352239KFT
R18 R23 R25 R26 R30 R32 R111 R113 R126 R128 = -R-ERA3AEB223V
R19 R21 R27-R29 R31 = -R-ERA3AEB2942V
R20 = -R-ERJ3EKF2201V
R24 = -R-RK73H1JTTD1003F
R33 R38 R46 R51 R59 R64 = -R-RK73H1JTTD6200F
R34 R36 R39 R41 R47 R49 R52 R54 R60 R62 R65 R67 = -R-RK73H2ARTTD10R0F
R43 R44 R56 R57 R69 R70 = -R-ERJ3EKF6802V
R45 R58 R71 = -R-ERJ3EKF1802V
R72 R73 R75-R78 R87-R92 R102 R105-R109 R117-R122 = -R-ERA3AEB184V
R79 R86 R93 R101 R103 R116 R123 R131 = -R-NC_R1005
R80 R82 R95 R97 = -R-ERA3AEB361V
R81 R83 R96 R98 = -R-ERA3AEB273V
R104 R115 R124 R130 = -R-ERA3AEB7152V
R110 R112 R125 R127 = -R-ERA3AEB431V
R139 = -R-RK73B2ATTD103J
R141 = -R-ERJ3EKF3900V
R143 = -R-ERJ3EKF3901V
R144 R145 = -R-NC_R1608
R146-R149 = -R-ERA3ARB363V
RLY1-RLY3 = -RLY-G2RL-1A4-E-CF_DC24
TB1-TB6 = -TB-OT-264
TP1-TP56 TP62-TP64 = -TP-HK-3-G
ZD1 = -ZD-SMBJ30A_AC
ZNR1-ZNR3 = -ZNR-TND14V-751KB00AAA0

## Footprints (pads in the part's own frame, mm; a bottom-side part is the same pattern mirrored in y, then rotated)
_C_D_E22_5D0_8W9H18L_1
  round 3 hole 1: 1(-11.25,0) 2(11.25,0)
_D_S_EMD3_SOT_416_SC_1
  custom 0.125x0.125 smd: A(-0.75,0.5) C(-0.75,-0.5) C/A(0.75,0)
_D_S_SMB_DO_214AA_AC
  custom 0.5x0.5 smd: A(-2.05,0) C(2.05,0)
_IC_SOP5_P_0_95_DDC
  custom 0.125x0.125 smd: 1(1.2,-0.95) 2(1.2,0) 3(1.2,0.95) 4(-1.2,0.95) 5(-1.2,-0.95)
_ZNR_D_TND14V_16_0_7_1
  round 2 hole 1: 1(-3.75,1.65) 2(3.75,-1.65)
C_D_10_0_CD45_D9_0_T_1
  round 1.6 hole 0.8: 1(-5,0) 2(5,0)
C_D_F340X1_L42_W30_H_1
  round 2 hole 1.2: 1(-18.75,0) 2(18.75,0)
C_S_1005
  custom 0.113x0.113 smd: 1(-0.475,0) 2(0.475,0)
C_S_1608
  custom 0.2x0.2 smd: 1(-0.8,0) 2(0.8,0)
C_S_2012
  custom 0.2x0.2 smd: 1(-0.9,0) 2(0.9,0)
C_S_3225
  custom 0.3x0.3 smd: 1(-1.4,0) 2(1.4,0)
C_S_4532_T2_5
  custom 0.3x0.3 smd: 1(-2.15,0) 2(2.15,0)
C_S_6050_CA572_TDK
  custom 0.45x0.45 smd: 1(-3.15,0) 2(3.15,0)
CA_D_D25_0_L55_0_MXK
  round 3 hole 2: 1(-3.535,-3.535) 2(3.535,3.535)
CA_S_D12_5_L13_160CL_1
  custom 0.625x0.625 smd: 1(-5.15,0) 2(5.15,0)
  custom 1.05x1.05 smd: NC1(0,-4.9) NC2(0,4.9)
CN_D_B02B_PASK
  round 1.4 hole 0.8: 1(1,0) 2(-1,0)
CN_S_6_1460820_X_SP__1
  custom 0.4x0.4 smd: G1(-0.8,-1.75) G2(-0.8,1.75)
  custom 0.35x0.35 smd: S(1.85,0)
CN_S_BM02B_PASS_1_TF_1
  round 0.01 hole 1.9x0.9 unplated: (-3.2,2.05)
  round 0.01 hole 0.9 unplated: (3.2,2.05)
  custom 0.25x0.25 smd: 1(1,3.3) 2(-1,3.3)
  custom 0.45x0.45 smd: NC1(3.35,-1.35) NC2(-3.35,-1.35)
CN_S_WR_60S_VFH05_N1
  custom 0.156x0.156 smd: 1(-7.438,-2.1) 2(-7.438,2.1) 59(7.438,-2.1) 60(7.438,2.1)
  custom 0.062x0.062 smd: 3(-6.75,-2.1) 4(-6.75,2.1) 5(-6.25,-2.1) 6(-6.25,2.1) 7(-5.75,-2.1) 8(-5.75,2.1) 9(-5.25,-2.1) 10(-5.25,2.1) 11(-4.75,-2.1) 12(-4.75,2.1) 13(-4.25,-2.1) 14(-4.25,2.1) 15(-3.75,-2.1) 16(-3.75,2.1) 17(-3.25,-2.1) 18(-3.25,2.1) 19(-2.75,-2.1) 20(-2.75,2.1) 21(-2.25,-2.1) 22(-2.25,2.1) 23(-1.75,-2.1) 24(-1.75,2.1) 25(-1.25,-2.1) 26(-1.25,2.1) 27(-0.75,-2.1) 28(-0.75,2.1) 29(-0.25,-2.1) 30(-0.25,2.1) 31(0.25,-2.1) 32(0.25,2.1) 33(0.75,-2.1) 34(0.75,2.1) 35(1.25,-2.1) 36(1.25,2.1) 37(1.75,-2.1) 38(1.75,2.1) 39(2.25,-2.1) 40(2.25,2.1) 41(2.75,-2.1) 42(2.75,2.1) 43(3.25,-2.1) 44(3.25,2.1) 45(3.75,-2.1) 46(3.75,2.1) 47(4.25,-2.1) 48(4.25,2.1) 49(4.75,-2.1) 50(4.75,2.1) 51(5.25,-2.1) 52(5.25,2.1) 53(5.75,-2.1) 54(5.75,2.1) 55(6.25,-2.1) 56(6.25,2.1) 57(6.75,-2.1) 58(6.75,2.1)
D_D_TO_247_3_1A2C3A
  round 2.3 hole 1.5: 1(-5.45,0) 2(0,0) 3(5.45,0)
D_D_TO_247_3_1A2C3A__1
  round 2.3 hole 1.5: 1(-5.45,-8.09) 2(0,0) 3(5.45,0)
D_S_1_1E1A_USC_AC
  custom 0.2x0.2 smd: A(-1.15,0) C(1.15,0)
F_D_0505XXXX_10A_16A
  round 1.8 hole 1: 1(-19.5,0) 2(19.5,0)
IC_D_LD20_26BXX
  round 2.3 hole 1.5: 2(-31,0) 3(-31,-20) 4(31,-11.5) 8(31,11.5)
IC_D_MEF1_SP3C
  round 1.6 hole 0.8: 1(-8.825,1.535) 2(-6.285,1.535) 5(1.335,1.535) 7(6.415,1.535)
IC_D_RXXP2XXS
  round 1.6 hole 0.8: 1(-7.85,0) 2(-5.31,0) 5(2.31,0) 7(7.39,0)
IC_SOP4_2_54_11_4M1S
  custom 0.2x0.2 smd: 1(-1.27,-3.15) 3(1.27,-3.15) 4(1.27,3.15) 6(-1.27,3.15)
IC_SOP5_0_95_SOT_25
  custom 0.125x0.125 smd: 1(-0.95,-1.2) 2(0,-1.2) 3(0.95,-1.2) 4(0.95,1.2) 5(-0.95,1.2)
IC_SOP6_0_65_DCK
  custom 0.087x0.087 smd: 1(-0.65,-0.95) 2(0,-0.95) 3(0.65,-0.95) 4(0.65,0.95) 5(0,0.95) 6(-0.65,0.95)
IC_SOP6_1_27_11_4N10_1
  custom 0.163x0.163 smd: 1(-1.27,-5.1) 2(0,-5.1) 3(1.27,-5.1) 4(1.27,5.1) 5(0,5.1) 6(-1.27,5.1)
IC_SOP8_1_27_D
  custom 0.163x0.163 smd: 1(-1.905,-2.435) 2(-0.635,-2.435) 3(0.635,-2.435) 4(1.905,-2.435) 5(1.905,2.435) 6(0.635,2.435) 7(-0.635,2.435) 8(-1.905,2.435)
IC_SOP8_2_54_11_10C4_1
  custom 0.375x0.375 smd: 1(-3.81,-5.3) 2(-1.27,-5.3) 3(1.27,-5.3) 4(3.81,-5.3) 5(3.81,5.3) 6(1.27,5.3) 7(-1.27,5.3) 8(-3.81,5.3)
IC_SOP20_0_65_FT
  custom 0.131x0.131 smd: 1(-3.013,-2.9) 10(3.013,-2.9) 11(3.013,2.9) 20(-3.013,2.9)
  custom 0.087x0.087 smd: 2(-2.275,-2.9) 3(-1.625,-2.9) 4(-0.975,-2.9) 5(-0.325,-2.9) 6(0.325,-2.9) 7(0.975,-2.9) 8(1.625,-2.9) 9(2.275,-2.9) 12(2.275,2.9) 13(1.625,2.9) 14(0.975,2.9) 15(0.325,2.9) 16(-0.325,2.9) 17(-0.975,2.9) 18(-1.625,2.9) 19(-2.275,2.9)
L_D_CFA37H_40210R0
  round 2.5 hole 1.7: 1(-7.353,20.203) 2(-21.173,-3.733) 3(-13.82,-16.47) 4(13.82,-16.47) 5(21.173,-3.733) 6(7.353,20.203)
L_D_HKBS_24D160
  round 2.6 hole 1.8: 1(0,-17) 2(0,17)
L_S_1005
  custom 0.113x0.113 smd: 1(-0.475,0) 2(0.475,0)
L_S_ACT1210
  custom 0.15x0.15 smd: 1(-1.525,0.5) 2(-1.525,-0.5) 3(1.525,-0.5) 4(1.525,0.5)
L_S_MBKK1608
  custom 0.138x0.138 smd: 1(-0.625,0) 2(0.625,0)
LED_S_1608_AC
  custom 0.2x0.2 smd: A(-0.8,0) C(0.8,0)
PS_D_EC5SAW
  round 1.6 hole 0.8: 1(-8.9,1.25) 2(-6.4,1.25) 3(-3.9,1.25) 6(3.9,1.25) 7(6.4,1.25) 8(8.9,1.25)
Q_D_TO_247_3_GDS_TO__1
  round 2.3 hole 1.5: D(0,0) G(-5.45,-8.4) S(5.45,-8.4)
Q_S_SOT_23F_GSD
  custom 0.2x0.2 smd: D(0,1.05) G(-0.95,-1.05) S(0.95,-1.05)
R_D_MNG12E
  round 2 hole 1.2: 1(-4.75,0) 2(4.75,0)
R_D_RCR60_9_5X3_5
  round 2 hole 1: 1(-10.16,0) 2(10.16,0)
R_S_1005
  custom 0.113x0.113 smd: 1(-0.475,0) 2(0.475,0)
R_S_1608
  custom 0.2x0.2 smd: 1(-0.8,0) 2(0.8,0)
R_S_2012
  custom 0.2x0.2 smd: 1(-0.9,0) 2(0.9,0)
R_S_6432_T1_25
  custom 0.487x0.487 smd: 1(-2.725,0) 2(2.725,0)
RL_D_G2RL_6PIN
  round 2.1 hole 1.3: 1(-12.2,-3.75) 3(7.8,-3.75) 4(12.8,-3.75) 5(12.8,3.75) 6(7.8,3.75) 8(-12.2,3.75)
TB_D_OT_264
  oval 3.5x7 hole 1.5x5: 1(-4.4,0) 2(4.4,0)
TP_HK_3_G
  custom 0.425x0.425 smd: 1(0,0)
unnamed
  round 0.01 hole 3.5 unplated: (0,0)
unnamed#2
  round 0.01 hole 3.5 unplated: (-48,-1) (68,-1)

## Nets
5V: C23.1 C24.1 C25.1 C35.1 C37.1 C38.1 C39.1 C48.1 C51.1 C85.1 C89.1 C93.1 C97.1 C98.1 C99.1 C101.1 C107.1 C114.1 C115.1 C116.1 C117.1 C118.1 C119.2 C121.1 C122.1 C123.1 C124.1 C125.1 C126.1 C127.1 C128.1 C129.1 C140.1 C141.1 C142.1 C143.1 C144.1 C146.1 C147.1 C149.1 C150.1 CN9.1 CN9.2 CN9.3 CN9.4 CT1.8 CT2.8 CT3.8 D10.C IC1.3 IC1.4 IC2.5 IC8.8 IC9.8 IC10.5 IC12.8 IC13.8 IC14.20 IC15.20 IC16.5 IC17.5 IC18.5 IC19.5 IC20.5 IC21.5 IC22.5 IC23.5 IC24.5 IC28.5 IC29.5 IC30.5 IC31.6 IC32.6 IC33.6 IC34.6 IC35.6 IC36.6 PS2.6 PS6.1 PS7.1 R13.1 R20.2 R33.1 R38.1 R46.1 R51.1 R59.1 R64.1 R132.2 R133.2 R134.2 R135.2 R136.2 R137.2 R138.2 TP7.1 TP53.1 TP55.1
24V: C1.1 C8.1 C12.1 C19.1 C20.1 C21.1 C62.1 C70.1 C78.1 CN1.1 D1.C D2.C D3.C L3.1 PS3.1 PS4.1 PS5.1 R10.2 R11.1 R139.2 R140.2 RLY1.1 RLY2.1 RLY3.1 TP4.1 TP6.1 ZD1.C
+5V_AC: C84.1 C88.1 C94.1 C95.1 C96.1 D17.C D18.C IC8.1 IC9.1 PS6.7 R144.2 TP35.1
+5V_DC: C103.1 C106.1 C111.1 C112.1 C113.1 D19.C D20.C IC12.1 IC13.1 PS7.7 R145.2 TP42.1
+10V_U: C58.1 C60.1 C65.1 IC4.1 PC1.6 PC2.6 R43.2 TP20.1
+10V_V: C66.1 C68.1 C73.1 IC5.1 PC3.6 PC4.6 R56.2 TP25.1
+10V_W: C74.1 C76.1 C81.1 IC6.1 PC5.6 PC6.6 R69.2 TP30.1
GND: C23.2 C24.2 C25.2 C35.2 C37.2 C38.2 C39.2 C48.2 C50.2 C51.2 C52.2 C53.2 C85.2 C89.2 C93.2 C97.2 C98.2 C99.2 C101.2 C105.2 C107.2 C108.1 C114.2 C115.2 C116.2 C117.2 C118.2 C120.2 C121.2 C122.2 C123.2 C124.2 C125.2 C126.2 C127.2 C128.2 C129.2 C140.2 C141.2 C142.2 C143.2 C144.2 C146.2 C147.2 C149.2 C150.2 CN8.2 CN9.5 CN9.6 CN9.7 CN9.8 CN9.11 CN9.12 CN9.15 CN9.16 CN9.19 CN9.20 CN9.23 CN9.24 CN9.31 CN9.32 CN9.39 CN9.40 CN9.50 CN9.59 CN9.60 CT1.5 CT2.5 CT3.5 D10.A IC1.2 IC2.2 IC8.5 IC9.5 IC10.2 IC12.5 IC13.5 IC14.1 IC14.8 IC14.9 IC14.10 IC14.19 IC15.1 IC15.3 IC15.4 IC15.5 IC15.6 IC15.7 IC15.8 IC15.9 IC15.10 IC15.19 IC16.2 IC17.2 IC18.2 IC19.2 IC20.2 IC21.2 IC22.2 IC23.2 IC24.2 IC28.2 IC29.2 IC30.2 IC31.2 IC32.2 IC33.2 IC34.2 IC35.2 IC36.2 L14.1 L14.2 L15.1 L15.2 L16.1 L16.2 L17.1 L17.2 LED2.C PC7.3 PS2.7 PS6.2 PS7.2 R24.1 R115.1 R124.2 R142.1 TP9.1 TP52.1 TP54.1
GND_5VAC: C84.2 C88.2 C94.2 C95.2 C96.2 IC8.4 IC9.4 PS6.5 R84.2 R99.2 R144.1 TP37.1
GND_5VDC: C103.2 C106.2 C111.2 C112.2 C113.2 IC12.4 IC13.4 PS7.5 R114.2 R129.2 R145.1 TP43.1
GND_24V: C1.2 C8.2 C12.2 C19.2 C20.2 C21.2 C22.2 C62.2 C70.2 C78.2 C120.1 CN1.2 LED1.C PS2.1 PS3.2 PS4.2 PS5.2 Q7.S R12.2 R143.1 TP5.1 TP8.1 ZD1.A
/DO1_BI: CN9.42 IC15.2 R138.1
/MAINRLY_24V: D1.A D2.A D3.A Q7.D R139.1 RLY1.8 RLY2.8 RLY3.8 TP50.1
/PWM1A_BI: CN9.25 IC14.2 R132.1
/PWM1B_BI: CN9.26 IC14.3 R133.1
/PWM2A_BI: CN9.27 IC14.4 R134.1
/PWM2B_BI: CN9.28 IC14.5 R135.1
/PWM3A_BI: CN9.29 IC14.6 R136.1
/PWM3B_BI: CN9.30 IC14.7 R137.1
/PWM_U_A: IC14.18 PC1.3 R35.2 TP44.1
/PWM_U_B: IC14.17 PC2.3 R40.2 TP45.1
/PWM_V_A: IC14.16 PC3.3 R48.2 TP46.1
/PWM_V_B: IC14.15 PC4.3 R53.2 TP47.1
/PWM_W_A: IC14.14 PC5.3 R61.2 TP48.1
/PWM_W_B: IC14.13 PC6.3 R66.2 TP49.1
AC_L_IN_W: L2.6 PS1.3 R9.2 RLY3.4 RLY3.5
AC_N_IN: L2.4 PS1.2 R6.2 RLY2.4 RLY2.5
AC_U: C6.1 C7.1 CT1.3 CT1.4 R1.1 R75.1 RLY1.3 RLY1.6 TP1.1
AC_V: C6.2 C9.1 C86.2 C91.2 CT2.3 CT2.4 L10.2 L11.2 R6.1 R80.1 R86.1 R95.1 R101.1 RLY2.3 RLY2.6 TP2.1
AC_W: C7.2 C9.2 CT3.3 CT3.4 R9.1 R87.1 RLY3.3 RLY3.6 TP3.1
AD0: CN9.9 IC16.1 IC16.4 TP31.1
AD1: CN9.10 IC18.1 IC18.4 TP34.1
AD2: CN9.13 IC21.1 IC21.4 TP38.1
AD3: CN9.14 IC23.1 IC23.4 TP41.1
AD4: CN9.17 IC31.3 IC31.4 TP13.1
AD5: CN9.18 IC33.3 IC33.4 TP14.1
AD6: CN9.21 IC35.3 IC35.4 TP15.1
AD7: CN9.22 IC2.1 IC2.4 TP10.1
FG: C13.2 C14.2 C15.2 C16.2 C17.2 C18.2 TB4.1 TB4.2
GATE_U_A: C59.1 CN2.S D11.A Q1.G R36.2 R37.2 TP16.1
GATE_U_B: C61.1 CN3.S D12.A Q2.G R41.2 R42.2 TP18.1
GATE_V_A: C67.1 CN4.S D13.A Q3.G R49.2 R50.2 TP21.1
GATE_V_B: C69.1 CN5.S D14.A Q4.G R54.2 R55.2 TP23.1
GATE_W_A: C75.1 CN6.S D15.A Q5.G R62.2 R63.2 TP26.1
GATE_W_B: C77.1 CN7.S D16.A Q6.G R67.2 R68.2 TP28.1
IU: CT1.7 R23.1
IV: CT2.7 R25.1
IW: CT3.7 R26.2
SIG193: C2.2 C10.1 C14.1 F2.2 L1.3 R2.1 R8.2 ZNR1.1 ZNR3.2
SOURCE_U: C58.2 C59.2 C60.2 C61.2 C63.2 C64.2 C65.2 CN2.G1 CN2.G2 CN3.G1 CN3.G2 IC4.3 IC4.4 PC1.4 PC2.4 PS3.5 Q1.S Q2.S R37.1 R42.1 R45.1 TP17.1 TP19.1
SOURCE_V: C66.2 C67.2 C68.2 C69.2 C71.2 C72.2 C73.2 CN4.G1 CN4.G2 CN5.G1 CN5.G2 IC5.3 IC5.4 PC3.4 PC4.4 PS4.5 Q3.S Q4.S R50.1 R55.1 R58.1 TP22.1 TP24.1
SOURCE_W: C74.2 C75.2 C76.2 C77.2 C79.2 C80.2 C81.2 CN6.G1 CN6.G2 CN7.G1 CN7.G2 IC6.3 IC6.4 PC5.4 PC6.4 PS5.5 Q5.S Q6.S R63.1 R68.1 R71.1 TP27.1 TP29.1
VDC_M: C26.2 C27.2 C28.2 C29.2 C30.2 C31.2 C32.2 C33.2 C34.1 C36.1 C40.1 C41.1 C42.1 C43.1 C44.1 C45.1 C104.2 C109.2 L12.2 L13.2 Q2.D Q4.D Q6.D R15.1 R16.2 R110.1 R116.1 R125.1 R131.1
VDC_N: C34.2 C36.2 C40.2 C41.2 C42.2 C43.2 C44.2 C45.2 D7.1 D7.3 D8.1 D8.3 D9.1 D9.3 R17.1 R117.1 TB6.1 TB6.2
VDC_P: C26.1 C27.1 C28.1 C29.1 C30.1 C31.1 C32.1 C33.1 D4.2 D5.2 D6.2 R14.2 R105.1 TB5.1 TB5.2
VREF: C50.1 IC1.5 IC10.3 IC20.3 IC28.3 IC29.3 IC30.3 TP11.1
VREF_AC_UV: C151.2 IC10.1 IC10.4 R146.1 TP36.1
VREF_AC_WV: C153.2 IC20.1 IC20.4 R148.1 TP56.1
VREF_IN_U: C47.1 CT1.6 IC28.1 IC28.4 R18.1 R21.2 TP62.1
VREF_IN_V: C54.1 CT2.6 IC29.1 IC29.4 R28.2 R30.1 TP63.1
VREF_IN_W: C55.2 CT3.6 IC30.1 IC30.4 R27.1 R32.1 TP64.1
N01434: F1.1 TB1.1 TB1.2
N01736: F2.1 TB2.1 TB2.2
N01804: F3.1 TB3.1 TB3.2
N02981: C3.2 C10.2 C15.1 F3.2 L1.5 R3.1 R8.1 ZNR2.1 ZNR3.1
N16767228: C4.2 C11.1 C17.1 L1.4 L2.3 R4.1 R7.2
N16767258: C2.1 C3.1 C13.1 F1.2 L1.1 R2.2 R3.2 ZNR1.2 ZNR2.2
N16767515: L2.2 R1.2 RLY1.4 RLY1.5
N16768979: C4.1 C5.1 C16.1 L1.2 L2.1 R4.2 R5.2
N16769631: C5.2 C11.2 C18.1 L1.6 L2.5 R5.1 R7.1
N16957930: LED1.A R11.2
N16958743: PS1.8 R12.1
N17056068: C22.1 C119.1 L3.2 PS2.2
N17056085: LED2.A R13.2
N17156262: PS1.4 R10.1
N17206598: R72.1 R75.2
N17206600: R72.2 R76.1
N17206602: R73.1 R76.2
N17206604: R73.2 R78.1
N17206606: R77.1 R78.2
N17206608: C86.1 L10.1 R77.2 R79.1 R80.2
N17206622: D17.A IC8.2 L10.4 R79.2 TP32.1
N17206634: C152.2 IC17.4 R83.2 R147.1
N17206741: IC8.7 R81.1
N17206751: C151.1 IC17.3 R81.2 R146.2
N17206765: L10.3 R82.1 R84.1 R86.2
N17206769: IC8.3 R82.2
N17206771: IC8.6 R83.1
N17207012: R87.2 R88.1
N17207014: R88.2 R89.1
N17207016: R89.2 R90.1
N17207018: R90.2 R91.1
N17207020: R91.2 R92.1
N17207022: C91.1 L11.1 R92.2 R93.1 R95.2
N17207036: D18.A IC9.2 L11.4 R93.2 TP33.1
N17207148: IC9.7 R96.1
N17207158: C153.1 IC19.3 R96.2 R148.2
N17207166: L11.3 R97.1 R99.1 R101.2
N17207170: IC9.3 R97.2
N17207172: IC9.6 R98.1
N17209468: R102.1 R105.2
N17209470: R102.2 R108.1
N17209472: R106.1 R108.2
N17209474: R106.2 R109.1
N17209476: R107.1 R109.2
N17209478: C104.1 L12.1 R103.1 R107.2 R110.2
N17209492: D19.A IC12.2 L12.4 R103.2 TP39.1
N17209611: IC12.7 R111.1
N17209621: C105.1 IC22.3 R111.2 R115.2
N17209635: L12.3 R112.2 R114.1 R116.2
N17209639: IC12.3 R112.1
N17209641: IC12.6 R113.1
N17209643: C102.2 IC22.4 R104.1 R113.2
N17209881: R117.2 R118.1
N17209883: R118.2 R119.1
N17209885: R119.2 R120.1
N17209887: R120.2 R121.1
N17209889: R121.2 R122.1
N17209891: C109.1 L13.1 R122.2 R123.1 R125.2
N17209905: D20.A IC13.2 L13.4 R123.2 TP40.1
N17210016: IC13.7 R126.1
N17210026: C108.2 IC24.3 R124.1 R128.2
N17210034: L13.3 R127.2 R129.1 R131.2
N17210038: IC13.3 R127.1
N17210040: IC13.6 R128.1
N17225441: PC1.1 R33.2 R35.1
N17225495: PC1.5 R34.1 R36.1
N17225499: D11.C R34.2
N17225644: PC2.1 R38.2 R40.1
N17225700: PC2.5 R39.1 R41.1
N17225704: D12.C R39.2
N17225875: C63.1 C64.1 IC4.8 PS3.7
N17225891: IC4.7 R44.2 R45.2
N17225996: R43.1 R44.1
N17226910: PC3.1 R46.2 R48.1
N17226964: PC3.5 R47.1 R49.1
N17226968: D13.C R47.2
N17227113: PC4.1 R51.2 R53.1
N17227169: PC4.5 R52.1 R54.1
N17227173: D14.C R52.2
N17227344: C71.1 C72.1 IC5.8 PS4.7
N17227360: IC5.7 R57.2 R58.2
N17227465: R56.1 R57.1
N17228579: PC5.1 R59.2 R61.1
N17228633: PC5.5 R60.1 R62.1
N17228637: D15.C R60.2
N17228782: PC6.1 R64.2 R66.1
N17228838: PC6.5 R65.1 R67.1
N17228842: D16.C R65.2
N17229013: C79.1 C80.1 IC6.8 PS5.7
N17229029: IC6.7 R70.2 R71.2
N17229134: R69.1 R70.1
N17284402: D4.1 D4.3 D7.2 L5.2 Q1.D
N17284406: D6.1 D6.3 D8.2 L9.2 Q5.D
N17284446: CT1.1 CT1.2 L4.1
N17284454: L4.2 L5.1
N17284506: R14.1 R15.2
N17284767: CT2.1 CT2.2 L6.1
N17284778: L6.2 L7.1
N17284780: D5.1 D5.3 D9.2 L7.2 Q3.D
N17285020: R16.1 R17.2
N17285107: CT3.1 CT3.2 L8.1
N17285115: L8.2 L9.1
N17285579: IC1.1 TP12.1
N17285634: C52.1 CN8.1 R20.1 R22.2 R24.2
N17285636: C53.1 D10.C/A IC2.3 R22.1
N17427639: C154.2 IC19.4 R98.2 R149.1
N17427765: C154.1 IC18.3 IC19.1 R149.2
N17430423: C152.1 IC16.3 IC17.1 R147.2
N17437974: C102.1 IC21.3 IC22.1 R104.2
N17438762: C110.2 IC23.3 IC24.1 R130.1
N17438821: C110.1 IC24.4 R126.2 R130.2
N17447576: IC15.18 R141.1 TP51.1
N17447582: PC7.1 R141.2 R142.2
N17447588: PC7.6 R140.1
N17447631: PC7.4 Q7.G R143.2
N17453034: C46.1 IC32.3 R18.2 R19.2
N17453159: C54.2 IC34.1 R25.2 R28.1
N17453191: C57.1 IC34.3 R30.2 R31.2
N17453904: C55.1 IC36.1 R26.1 R27.2
N17453936: C56.2 IC36.3 R29.1 R32.2
N17455071: C47.2 IC32.1 R21.1 R23.2
N17610632: C56.1 IC35.1 IC36.4 R29.2
N17611902: C57.2 IC33.1 IC34.4 R31.1
N17613182: C46.2 IC31.1 IC32.4 R19.1

Pads without a net: C20 NC1 NC2; CN8 NC1 NC2; CN9 33 34 35 36 37 38 41 43 44 45 46 47 48 49 51 52 53 54 55 56 57 58; IC4 2 5 6; IC5 2 5 6; IC6 2 5 6; IC14 11 12; IC15 11 12 13 14 15 16 17; IC31 5; IC32 5; IC33 5; IC34 5; IC35 5; IC36 5; PC1 2; PC2 2; PC3 2; PC4 2; PC5 2; PC6 2; PS2 3 8

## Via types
v1: diameter 1, hole 0.5, TOP to BOTTOM, 688 vias

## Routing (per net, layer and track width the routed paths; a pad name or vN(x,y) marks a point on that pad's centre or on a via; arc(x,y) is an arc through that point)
5V: length 295
  TOP w0.25: CN9.4 419.45,126.25 v1(418.5,125.3) ; CN9.3 426.2,126.25 426.5,125.95 426.5,125.26
  TOP w0.3: 93.55,82.45 93.55,81.85 93.45,81.75 93.45,81.19 ; 138.7,80.81 v1(138.7,79) ; 107.26,67.25 v1(105.75,67.25) ; IC32.6 82.6,87.15 82.75,87.3 83.31,87.3 ; 414.55,141.19 414.55,142.31 ; 107.45,67.44 107.45,68.05 107.05,68.45 107.05,68.95 ; 412.25,79.51 v1(412.25,78) ; 407.8,210.56 407.8,209.2 ; 407.8,209.2 407.8,206.75 C127.1 406.8,204.9 406.7,204.8 406.7,204.37 ; 407.8,209.2 406.7,209.2 ; 87.3,75.7 87.3,75.4 87.95,74.75 87.95,74.19 ; C128.1 422.55,210.75 v1(422.5,211.5) ; IC36.6 185.6,83.65 185.75,83.8 186.31,83.8 ; v1(130.5,81.75) 130.5,80.49 ; 104.81,72.45 104.05,72.45 v1(103.25,73.25) ; IC33.6 129.6,80.15 129.75,80.3 130.31,80.3 ; 414.55,145.69 414.55,146.81 ; PS6.1 152.75,96.67 152.6,96.53 151.66,96.53 ; C140.1 87.95,73.25 v1(87.75,72.5) ; 412.23,79.7 411.34,79.7 411.24,79.6 410.69,79.6 ; 118.51,71 v1(117,71) ; C149.1 186.5,78.25 186,78.75 v1(184.75,78.75) ; 130.31,86.55 129.75,86.55 129.6,86.4 IC34.6 ; 414.55,147.19 414.55,148.31 ; 420.95,208.45 422.25,208.45 ; 422.25,208.45 422.25,206 421.25,205 420.49,205 ; 422.25,208.45 422.55,208.75 422.55,209.85 ; 79.41,97 80.36,97 ; 414.55,144.19 414.55,145.31 ; C150.1 186.5,84.75 185.75,85.5 v1(184.75,85.5) ; IC35.6 185.6,77.4 185.75,77.55 186.31,77.55 ; 93.45,80.81 93.45,80.05 v1(94.25,79.25) ; v1(170,74.5) 169.08,74.5 168.78,74.2 C142.1 ; IC19.5 139.05,82.1 138.7,81.75 138.7,81.19 ; 436.69,214.45 437.43,214.45 C114.1 ; 105.19,72.45 106.2,72.45 IC1.3 ; 129.95,74.05 129.95,74.6 129.8,74.75 129.8,75.56 ; 118.3,72.95 118.3,72.21 118.7,71.81 118.7,71.19 ; 168.06,74.2 167.5,74.2 167.1,73.8 166.55,73.8 ; 133.55,82.45 133.55,82.1 133.2,81.75 133.2,81.19 ; IC31.6 82.75,81.65 82.9,81.8 C143.1 84.45,81.8 v1(85.25,81) 86.76,81 ; 86.95,81.19 86.95,81.75 87.3,82.1 IC16.5 ; 414.55,142.69 414.55,143.81 ; 415.7,112.3 415.7,112.9 415.8,113 415.8,113.81 ; 133.2,80.81 v1(133.2,79) ; 420.7,203.5 420.7,203.8 420.3,204.2 C129.1 ; C126.1 v1(407.75,212.25) ; v1(130,88.25) 130.5,87.75 130.5,86.67 ; 185.36,97 184.68,97 ; 129.36,97 128.57,97 ; v1(131.25,75.75) 129.99,75.75 ; 109.2,73.3 107.3,73.3 ; v1(412.75,87.75) 411.49,87.75 ; 83.5,87.49 v1(83.5,88.75)
  TOP w0.45: C97.1 151.66,96.53 ; C25.1 80.36,97 ; C39.1 185.36,97 ; C35.1 129.36,97
  TOP w0.5: IC14.20 400.84,142.49 400.45,142.1 400.45,140.28 ; 425.69,125.56 426.2,125.56 426.6,125.16 v1(426.6,124.3) ; IC30.5 166.55,73.8 ; v1(384.3,136.2) 379.77,136.2 ; 128.41,97 128.57,97 ; 128.41,97 128.41,94 ; 128.41,97 128.41,101.9 ; IC23.5 420.95,208.45 ; IC18.5 133.55,82.45 ; 378,240.93 v1(378,239.8) ; 379.77,160.2 v1(384.2,160.2) ; IC13.8 417.83,215.25 417.83,214.04 ; IC29.5 118.3,72.95 ; 129.41,94 128.41,94 ; 128.41,94 128.41,89.84 v1(130,88.25) ; 151.57,94.5 154.17,94.5 ; 144.7,94.28 144.7,95.41 144.31,95.8 144.31,97.65 ; IC21.5 406.7,209.2 ; 416.07,114 v1(417.4,114) ; 401.31,216.37 401.31,213.97 ; TP7.1 58.5,63 R13.1 58,61.3 v1(58,59) ; C107.1 v1(419.5,213.75) ; IC10.5 107.05,68.95 ; v1(97.7,91) 97.7,93.72 ; 401.58,213.69 v1(403.1,213.69) ; 379.77,54.2 v1(384.3,54.2) ; 417.07,103.5 v1(418.3,103.5) ; 97.7,94.28 97.7,96.56 97.31,97.37 ; IC1.4 109.2,73.3 ; 378,217.93 v1(378,216.8) ; v1(418.5,125.3) 419.54,125.3 419.8,125.56 420.31,125.56 ; 414.55,148.67 414.55,149.31 v1(414.45,149.9) ; IC17.5 93.55,82.45 ; 144.7,93.72 v1(144.7,81) ; 410.69,79.6 IC15.20 ; IC2.5 415.7,112.3 ; 379.77,78.2 v1(384.4,78.2) ; 107.3,73.3 IC1.3 ; IC20.5 129.95,74.05 ; 151.57,92.5 154.17,92.5 ; 400.45,139.72 v1(400.45,138.3) ; IC28.5 87.3,75.7 ; 420.7,203.5 IC24.5 ; 406.7,204.37 IC22.5 ; 185.58,94 184.74,94 ; D10.C v1(418.3,108.5)
  TOP w0.6: CT2.8 128.41,101.9 ; 184.5,97 184.5,94 ; 184.5,97 184.68,97 ; 184.5,97 184.5,98 184.91,98.41 CT3.8 ; 184.5,94 184.74,94 ; 184.5,94 184.5,92.55 v1(184.75,92) ; v1(79.5,91) 79.5,93 C24.1 79.41,95 CT1.8 ; 435,214.21 v1(435,213) 435,210.85 ; CN9.2 420.31,125.56 ; CN9.1 425.69,125.56 ; 436.5,214.21 v1(436.5,213) ; 156.65,86.5 154.83,86.5
  TOP w0.8: C128.1 422.55,209.85 ; 138.7,81.19 C124.1 138.7,80.81 ; C37.1 129.41,94 ; 420.49,205 C129.1 ; C126.1 407.8,210.56 ; R59.1 379.77,78.2 ; 97.7,93.72 C85.1 97.7,94.28 ; R132.2 414.55,141.19 ; 414.55,142.69 R133.2 414.55,142.31 ; 414.55,144.19 R134.2 414.55,143.81 ; C99.1 151.57,92.5 ; 118.7,71.19 C141.1 118.51,71 ; 186.31,77.55 C149.1 ; 436.5,214.21 C115.1 436.69,214.45 ; C38.1 185.58,94 ; 168.06,74.2 C142.1 ; 129.99,75.75 C125.1 129.8,75.56 ; C107.1 417.83,214.04 ; 107.45,67.44 C93.1 107.26,67.25 ; 144.7,94.28 C89.1 144.7,93.72 ; 86.95,81.19 C121.1 86.76,81 ; 130.31,80.3 C146.1 130.5,80.49 ; 414.55,145.69 R135.2 414.55,145.31 ; C98.1 151.57,94.5 ; C116.1 435,214.21 ; R46.1 379.77,160.2 ; 133.2,80.81 C123.1 133.2,81.19 ; 400.45,139.72 C117.1 400.45,140.28 ; 379.77,136.2 R51.1 ; 83.5,87.49 C144.1 83.31,87.3 ; R64.1 379.77,54.2 ; 93.45,81.19 C122.1 93.45,80.81 ; 412.25,79.51 C118.1 412.23,79.7 ; R20.2 417.07,103.5 ; 186.31,83.8 C150.1 ; R38.1 378,217.93 ; 415.8,113.81 C48.1 416.07,114 ; 414.55,148.31 R137.2 414.55,148.67 ; 130.5,86.67 C147.1 130.31,86.55 ; 411.49,87.75 R138.2 ; v1(58,59) 59.67,59 ; v1(60,56.5) 60.07,58.35 ; 414.55,146.81 R136.2 414.55,147.19 ; 104.81,72.45 C51.1 105.19,72.45 ; 401.31,213.97 C101.1 401.58,213.69 ; R33.1 378,240.93 ; 87.95,74.19 C140.1
  TOP w1: 154.47,94.5 154.47,92.5 ; 154.47,94.5 154.17,94.5 ; 154.47,94.5 PS6.1 ; 154.47,92.5 154.17,92.5 ; 154.47,92.5 154.47,90.56 154.5,90.53 154.5,86.5 ; 154.5,86.5 154.83,86.5 ; 154.5,86.5 v1(154.5,81) ; v1(436.5,213) v1(435,213) 430.89,213 PS7.1
  TOP w1.2: 60.07,58.35 C23.1 59.67,59 ; C119.2 57.65,39.5 ; C119.2 57.65,33.25 ; C119.2 59.5,36 ; 60.4,42.5 PS2.6 58.5,44.5
  TOP w1.5: IC9.8 144.31,97.65 ; IC8.8 97.31,97.37 ; IC12.8 401.31,216.37
  TOP w1.7: TP53.1 156.65,86.5 ; TP55.1 435,210.85
  CONDUCTIVE3 w0.5: PS2.6 59.4,45.5 ; PS2.6 61.4,43.5 ; PS2.6 61.4,45.5 ; PS2.6 59.4,43.5
  CONDUCTIVE3 w1: PS7.1 430.5,215.43 ; PS7.1 426.25,215.43 ; PS7.1 428.46,213.5
24V: length 159.1
  TOP w0.3: 27.3,71.05 27.3,70.19 ; 29.5,35.5 30.51,35.5 ; 30.7,34 30.7,35.31 ; 27.3,68.95 27.3,69.81 ; 30.7,37 30.7,35.69 ; 28.35,70 27.49,70 ; 32.7,71.05 32.7,70.19 ; 31.65,70 32.51,70 ; 32.7,68.9 32.7,69.81
  TOP w0.5: 170.93,86 171.75,86 173.25,87.5 RLY3.1 ; 113.84,86 115,86 116.25,87.25 RLY2.1 ; 62.92,73 v1(61.5,73) ; 170.65,85.72 170.65,84.35 C12.1 ; RLY1.1 64.65,89.2 64.65,85.28 ; C8.1 113.65,84.35 113.65,85.72 ; L3.1 46.5,31.38 ; L3.1 43.5,31.38 ; L3.1 45,30.25 ; 57.33,82 v1(56,82) ; C1.1 64.65,83.35 64.65,84.72
  TOP w0.6: CN1.1 31,63.5 ; CN1.1 32.5,62 ; CN1.1 32.5,65
  TOP w0.8: 27.3,69.81 R10.2 ; R10.2 27.3,70.19 ; R10.2 27.49,70 ; 32.51,70 C19.1 ; C19.1 32.7,69.81 ; C19.1 32.7,70.19 ; 64.65,85.28 D1.C 64.65,84.72 ; R139.2 57.33,82 ; R140.2 62.92,73 ; 30.7,35.31 R11.1 ; R11.1 30.51,35.5 ; R11.1 30.7,35.69 ; 170.65,85.72 D3.C 170.93,86 ; 113.84,86 D2.C 113.65,85.72 ; 47.98,63 v1(50.5,63)
  TOP w1: C21.1 36.5,28.85 ; C21.1 38.75,30.1 ; C21.1 34.45,30.1 ; TP4.1 22.5,40.65 ; TP4.1 22.5,44.35 ; TP4.1 24.7,42.5 ; TP4.1 20.3,42.5
  TOP w1.2: PS3.1 378.4,194.45 C62.1 v1(378.4,186.6) ; v1(378.4,27.6) C78.1 378.4,34.95 PS5.1 ; v1(378.4,108.3) C70.1 378.4,115.45 PS4.1
  TOP w1.5: ZD1.C v1(29.2,39.5) ; ZD1.C 31.45,42 ; ZD1.C 31.45,37.5 ; 26.25,53.5 26.25,47.75 ; C20.1 24.5,50.75
  TOP w1.7: TP6.1 47.98,63
  BOTTOM w0.6: CN1.1 32.5,65 ; CN1.1 31,63.5 ; CN1.1 32.5,62
  BOTTOM w1: PS5.1 378.75,36.5 ; PS5.1 376.85,38.25 ; PS5.1 376.85,34.75 ; PS3.1 378.75,196 ; PS3.1 376.85,197.75 ; PS3.1 376.85,194.25 ; PS4.1 376.85,118.75 ; PS4.1 378.75,117 ; PS4.1 376.85,115.25
  BOTTOM w1.5: RLY2.1 116.25,92.75 ; RLY2.1 114.25,94.8 ; RLY2.1 116.25,96.75 ; RLY3.1 170.95,91.8 ; RLY3.1 173.25,90 ; RLY3.1 173.25,94.1 ; RLY3.1 175.55,91.8 ; RLY1.1 67.25,89.5 ; RLY1.1 69.5,91.8 ; RLY1.1 65,91.8
  vias: v1(28,43.5) v1(28,40.5) v1(28,38) v1(28,35) v1(29,42) v1(29,36.5)
+5V_AC: length 33.7
  TOP w0.3: D18.C 143.1,110.85 143.56,111.31 144.12,111.31 ; 151.5,110.14 151.5,111.25
  TOP w0.45: C96.1 151.5,110.14
  TOP w0.5: 151.42,114.25 152.5,114.25 ; PS6.7 155.38,111 ; PS6.7 153.25,110.7 ; PS6.7 153.25,113.13 ; PS6.7 155.55,113 ; 151.42,112.75 152.5,112.75 ; 95.78,110.85 97.15,110.85 C84.1 97.31,110.76 97.31,108.63 ; 144.31,108.63 144.31,111.03 ; 151.45,115.86 152.5,115.86
  TOP w0.6: 97.82,111.2 v1(99,111.2) ; 152,117.75 152,120.02 ; 144.47,111.31 v1(145.6,111.31)
  TOP w0.8: 144.31,111.03 C88.1 ; C88.1 144.12,111.31 ; C88.1 144.47,111.31 ; C94.1 151.42,114.25 ; C84.1 97.82,111.2 ; D17.C 95.78,110.85 ; C95.1 151.42,112.75 ; R144.2 151.45,115.86
  TOP w1.5: IC8.1 97.31,108.63 ; IC9.1 144.31,108.63
  TOP w1.7: 152,120.02 TP35.1
  BOTTOM w1: PS6.7 154.47,113.72 ; PS6.7 152.66,111.92 ; PS6.7 156.26,111.92 ; PS6.7 154.47,110.11
  vias: v1(151.5,118.25)
+5V_DC: length 27
  TOP w0.3: 424.89,231 426.5,231
  TOP w0.45: C113.1 424.89,231
  TOP w0.5: 425.32,234.25 426.5,234.25 ; 425.32,232.5 426.5,232.5 ; D19.C C103.1 ; 418.08,230.31 v1(419.5,230.31) ; 401.57,230.31 v1(402.8,230.31) ; D20.C 416.8,230.35 C106.1 ; 417.81,227.63 417.81,230.03 ; 425.32,236 426.5,236 ; 401.31,227.63 401.31,230.03
  TOP w0.6: PS7.7 426.5,230.66 ; PS7.7 430.5,230.66 ; PS7.7 428.46,232.5 ; v1(431,235.25) TP42.1
  TOP w0.8: 417.81,230.03 C106.1 418.08,230.31 ; R145.2 425.32,236 ; C111.1 425.32,234.25 ; 401.31,230.03 C103.1 401.57,230.31 ; C112.1 425.32,232.5
  TOP w1.5: IC12.1 401.31,227.63 ; IC13.1 417.81,227.63
  vias: v1(427.5,235.25) v1(429.25,235.25)
+10V_U: length 32
  TOP w0.5: C58.1 363.62,244.73 364.85,244.73 ; C65.1 362.03,208.09 360.83,208.09 ; 363.25,244.82 v1(363.25,241) ; 362.75,214 363.25,214.5 ; 362.75,214 363.25,214 ; 362.75,214 362.07,214 ; 363.25,214.5 363.75,214 ; 363.25,214.5 363.25,214 ; 363.25,214.5 363.25,221.32 ; 363.25,214 363.75,214 ; 365.15,208.5 364.18,208.2 362.77,208.2 ; 365.5,208.85 v1(365.5,211.5) 365.5,213 364.5,214 363.75,214 ; C60.1 363.62,221.23 364.85,221.23
  TOP w0.6: PC1.6 364.85,244.73 ; IC4.1 360.83,208.09 ; PC2.6 364.85,221.23
  TOP w0.8: C60.1 363.25,221.32 ; C58.1 363.25,244.82 ; R43.2 362.07,214 ; C65.1 362.77,208.2
  TOP w1.7: 365.15,208.5 TP20.1 365.5,208.85
+10V_V: length 28.2
  TOP w0.5: 363.25,139.32 363.25,135.25 363,135 ; 363,135 365,133 v1(365,131.6) ; 363,135 360.07,135 ; 364.85,139.23 363.62,139.23 C68.1 ; 362.77,129.2 363.76,129.2 364.76,129 ; C66.1 363.62,163.23 364.85,163.23 ; 363.25,163.32 v1(363.25,159.5) ; 362.23,129.2 361.1,129.2 361,129.09 360.57,129.09
  TOP w0.6: IC5.1 360.57,129.09 ; PC3.6 364.85,163.23 ; PC4.6 364.85,139.23
  TOP w0.8: 362.23,129.2 C73.1 362.77,129.2 ; C66.1 363.25,163.32 ; R56.2 360.07,135 ; C68.1 363.25,139.32
  TOP w1: 365,129.35 v1(365,131.6)
  TOP w1.7: TP25.1 364.76,129
+10V_W: length 29
  TOP w0.5: C76.1 363.62,57.23 364.85,57.23 ; 360.07,53 362.8,53 ; 362.8,53 365,50.8 v1(365,49.4) ; 362.8,53 363.25,53.45 363.25,57.33 ; 364.85,81.23 363.62,81.23 C74.1 ; C81.1 361.53,47.09 360.33,47.09 ; 362.27,47.2 363.65,47.2 364.65,47 ; 363.25,81.33 v1(363.25,77.5)
  TOP w0.6: IC6.1 360.33,47.09 ; PC6.6 364.85,57.23 ; PC5.6 364.85,81.23
  TOP w0.8: C81.1 362.27,47.2 ; C74.1 363.25,81.33 ; R69.2 360.07,53 ; C76.1 363.25,57.33
  TOP w1: TP30.1 v1(365,49.4)
  TOP w1.7: 364.65,47 TP30.1
